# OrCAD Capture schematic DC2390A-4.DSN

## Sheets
1 PAGE1-HSMC: size Custom; title: OVER-SAMPLING ADC MULTI-APPLICATION; rev: 4; note: DEMO CIRCUIT 2390A
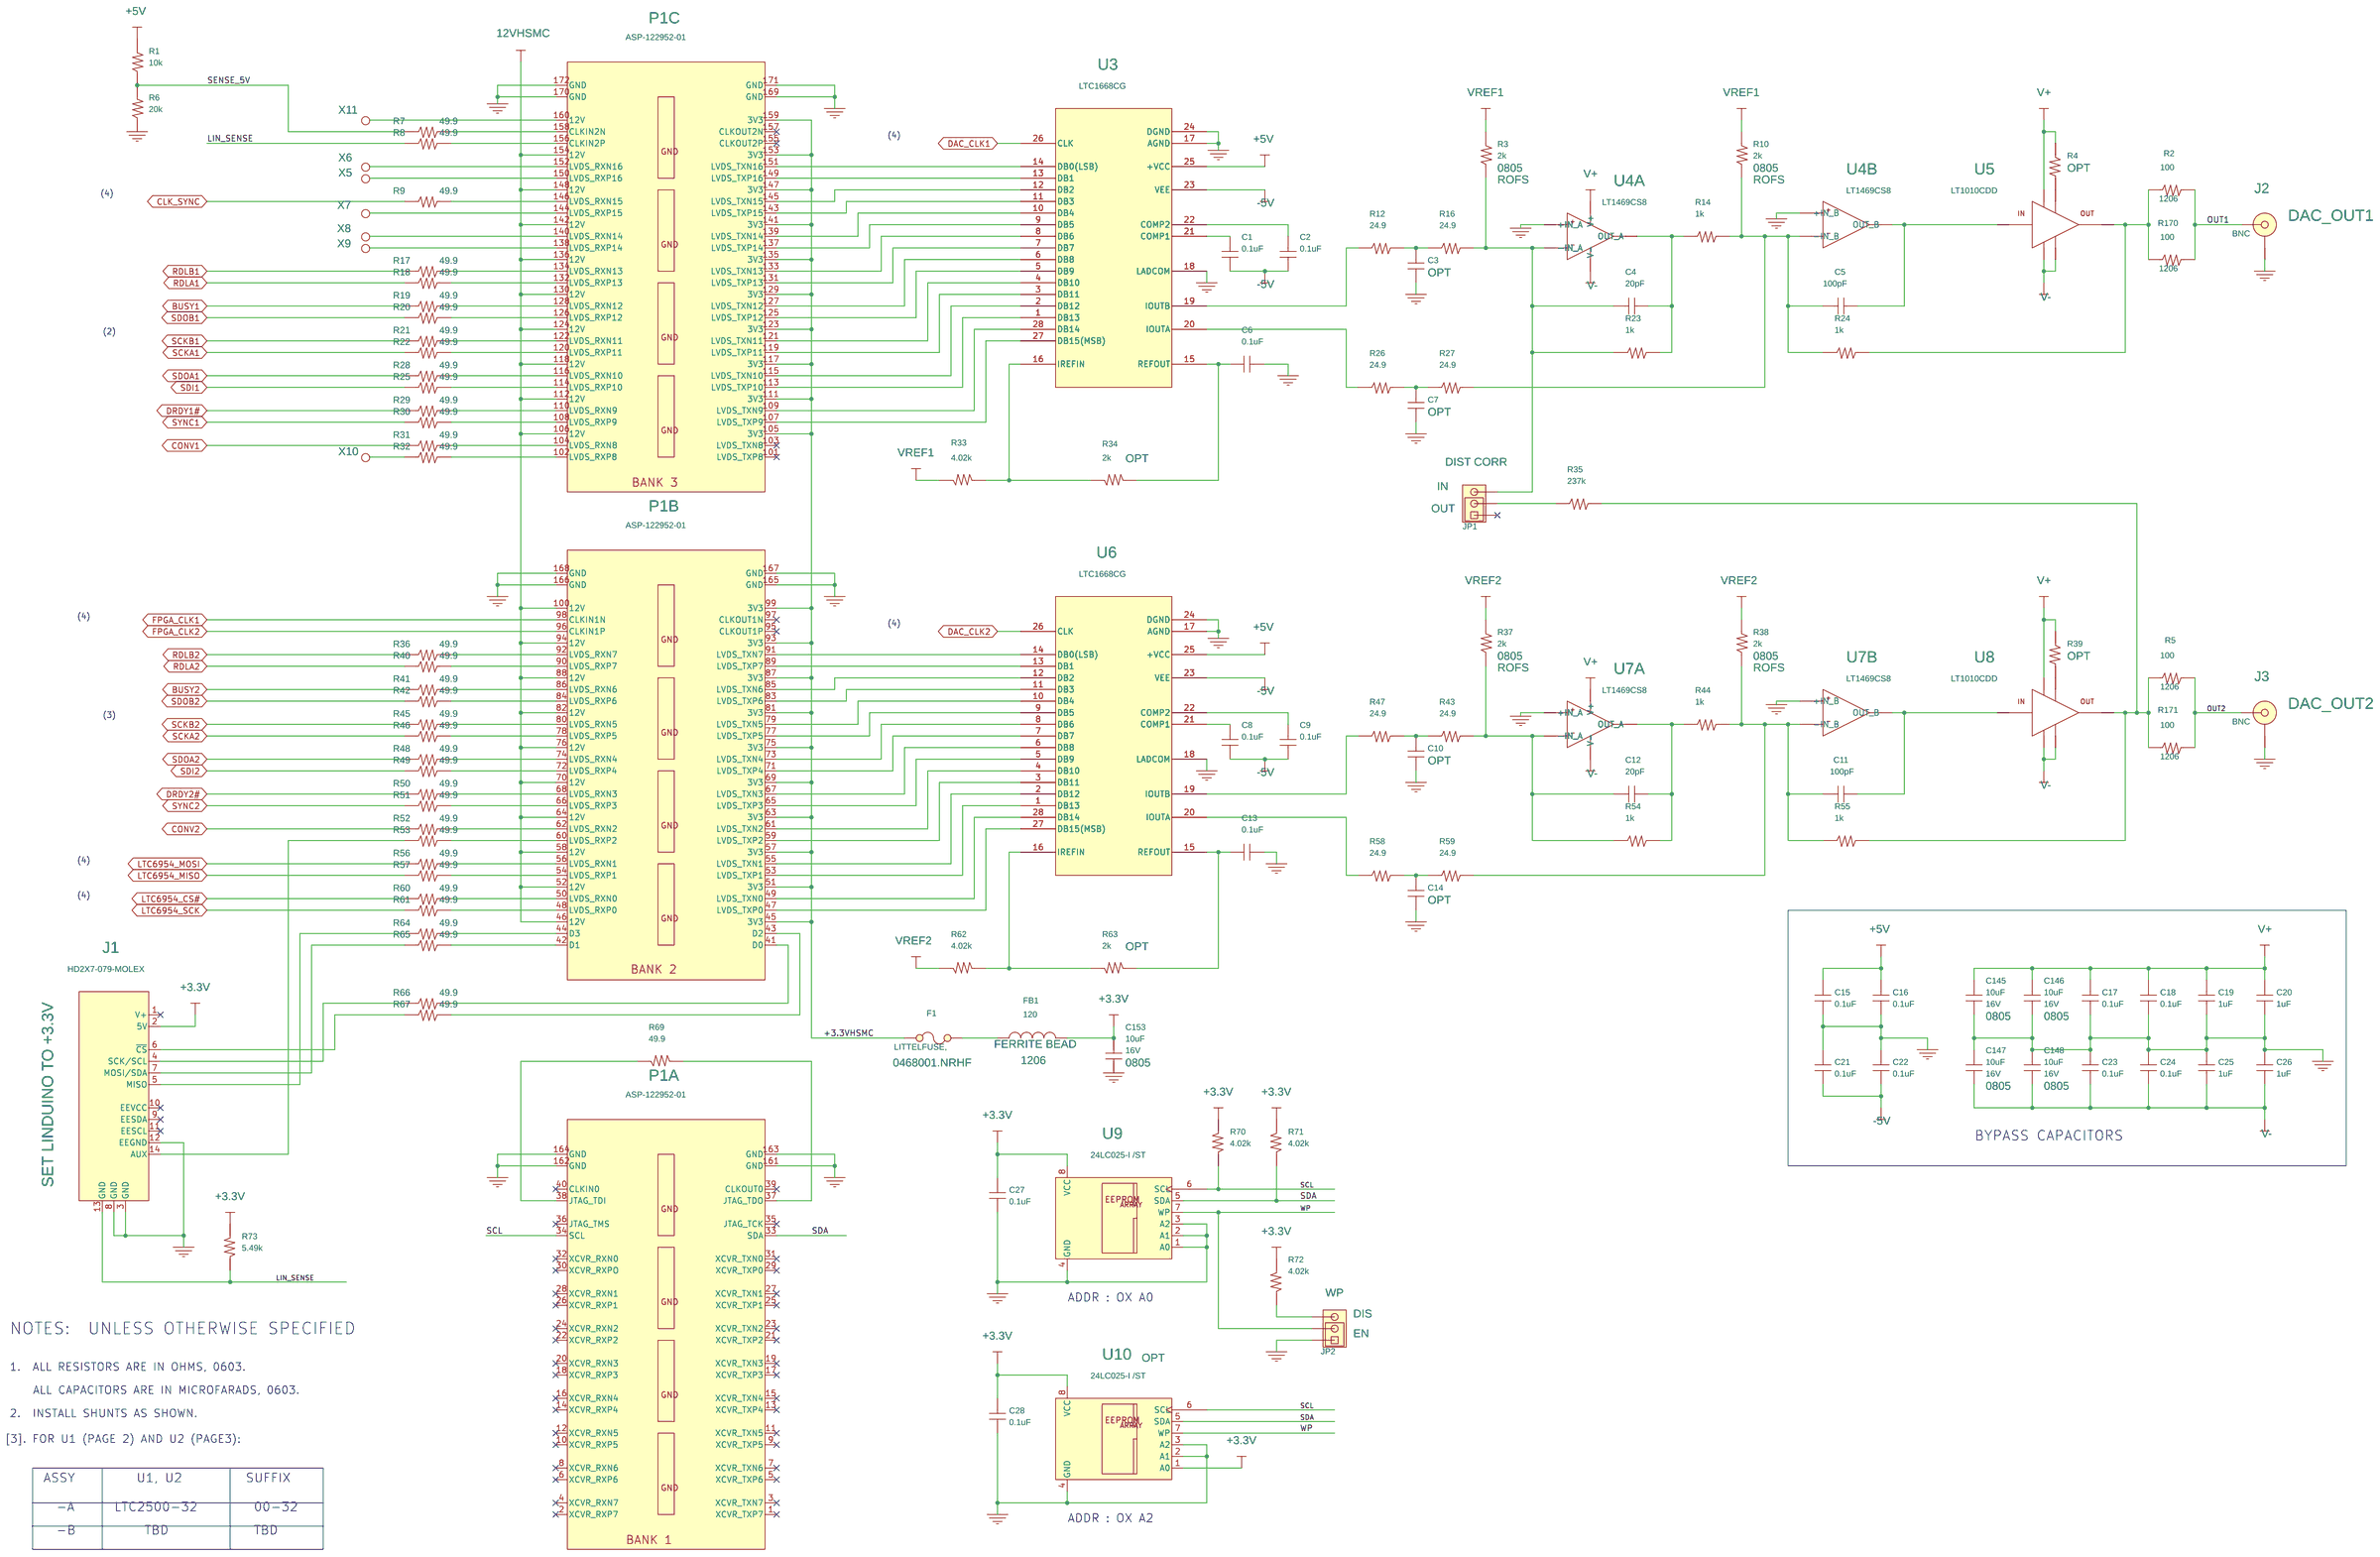
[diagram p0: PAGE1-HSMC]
2 PAGE2-20-BIT SAR ADC 1: size Custom
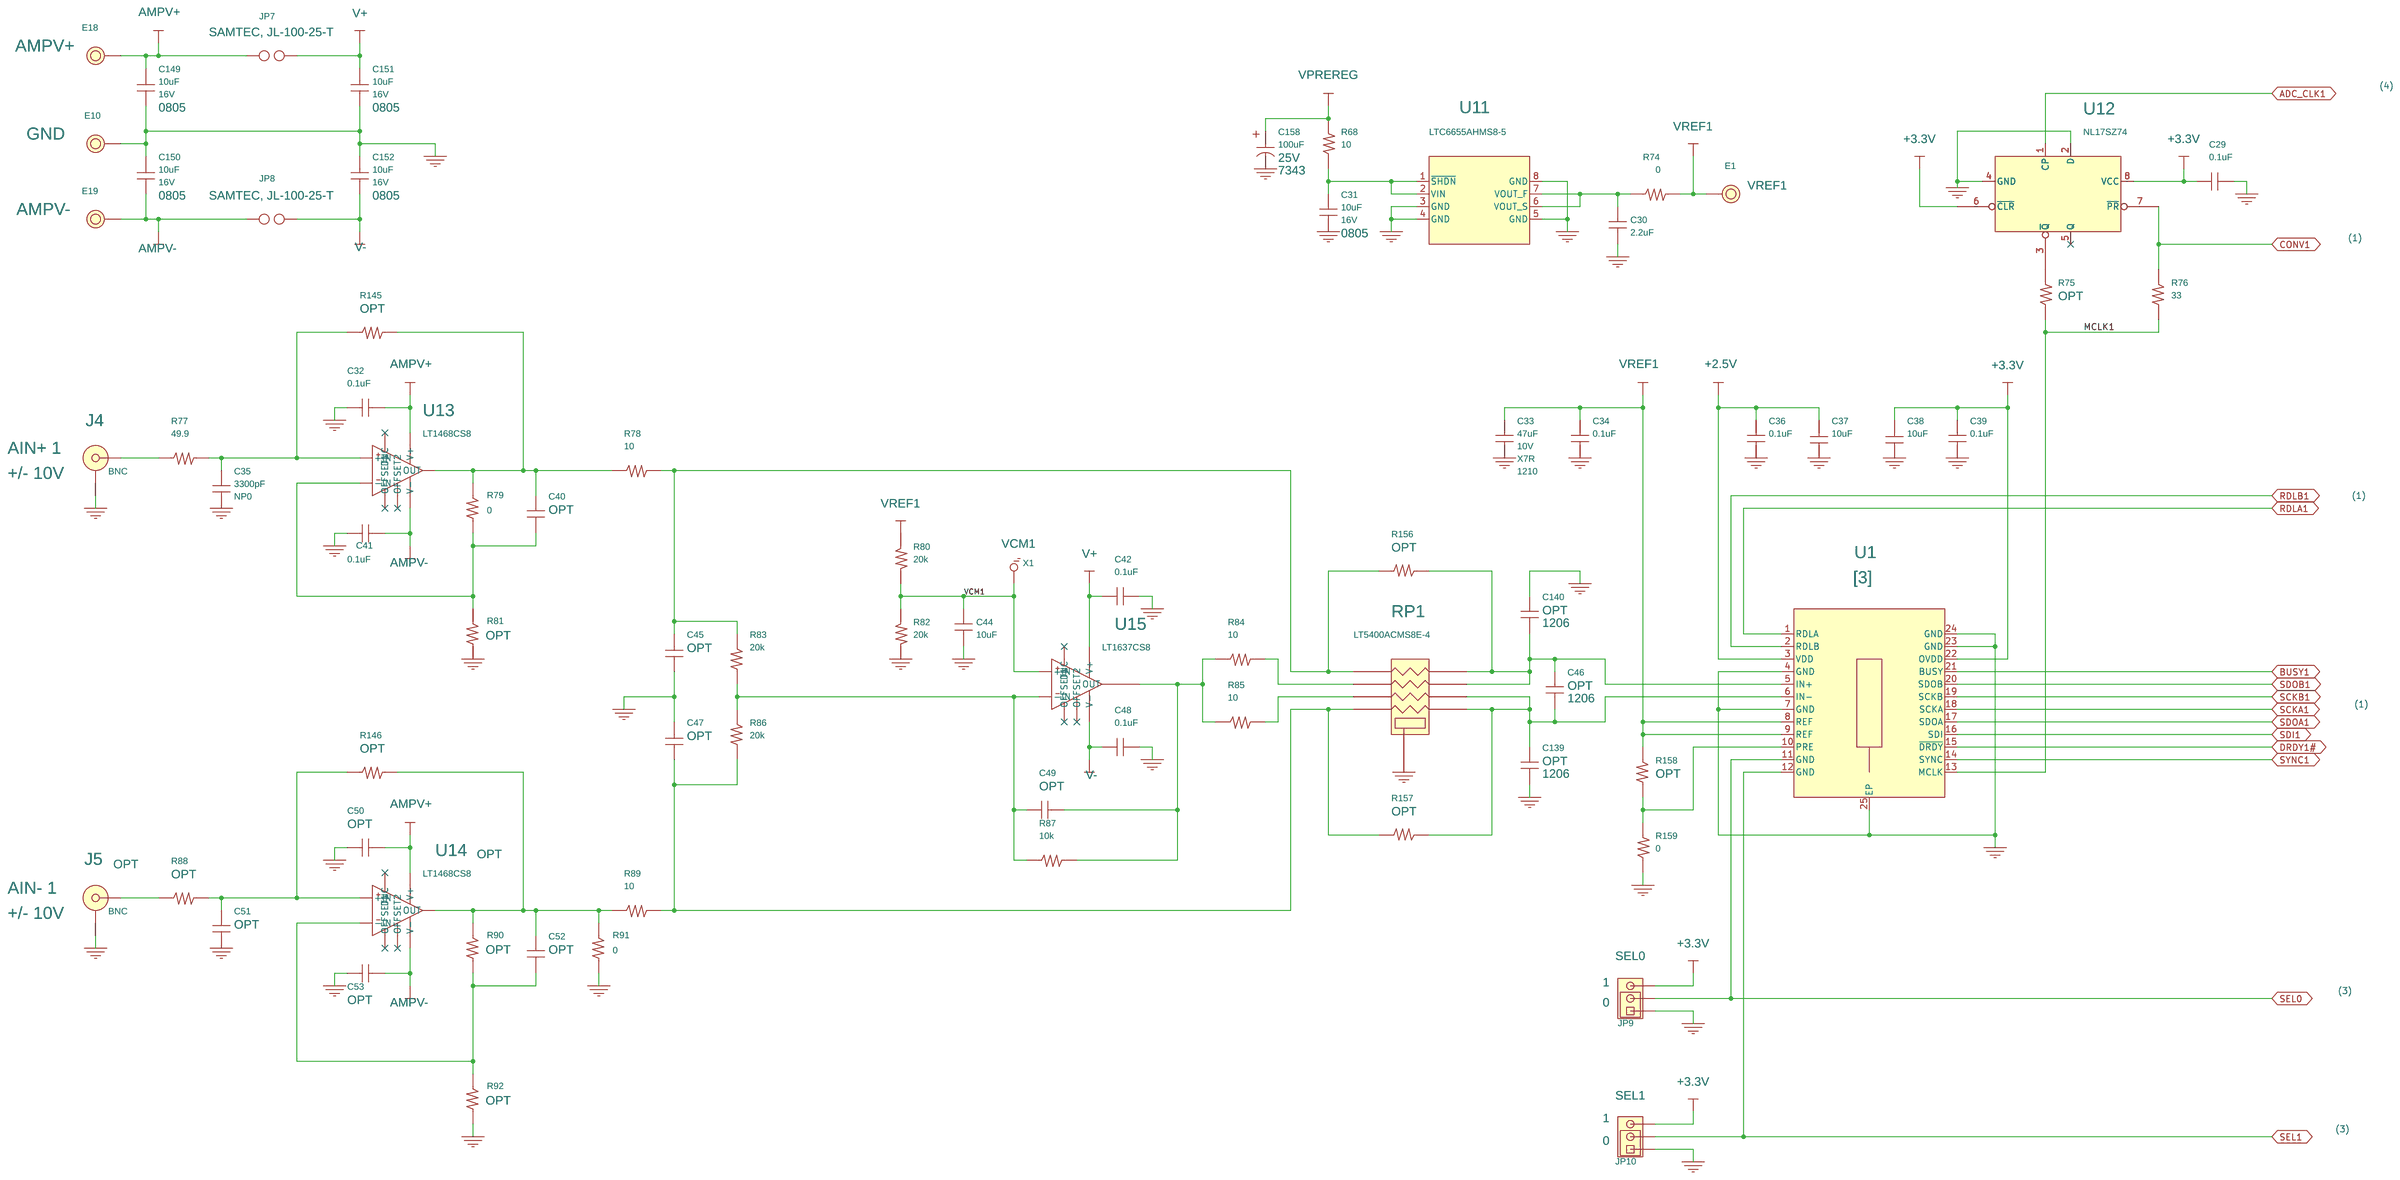
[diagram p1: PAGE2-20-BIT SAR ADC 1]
3 PAGE3-20-BIT SAR ADC 2: size Custom
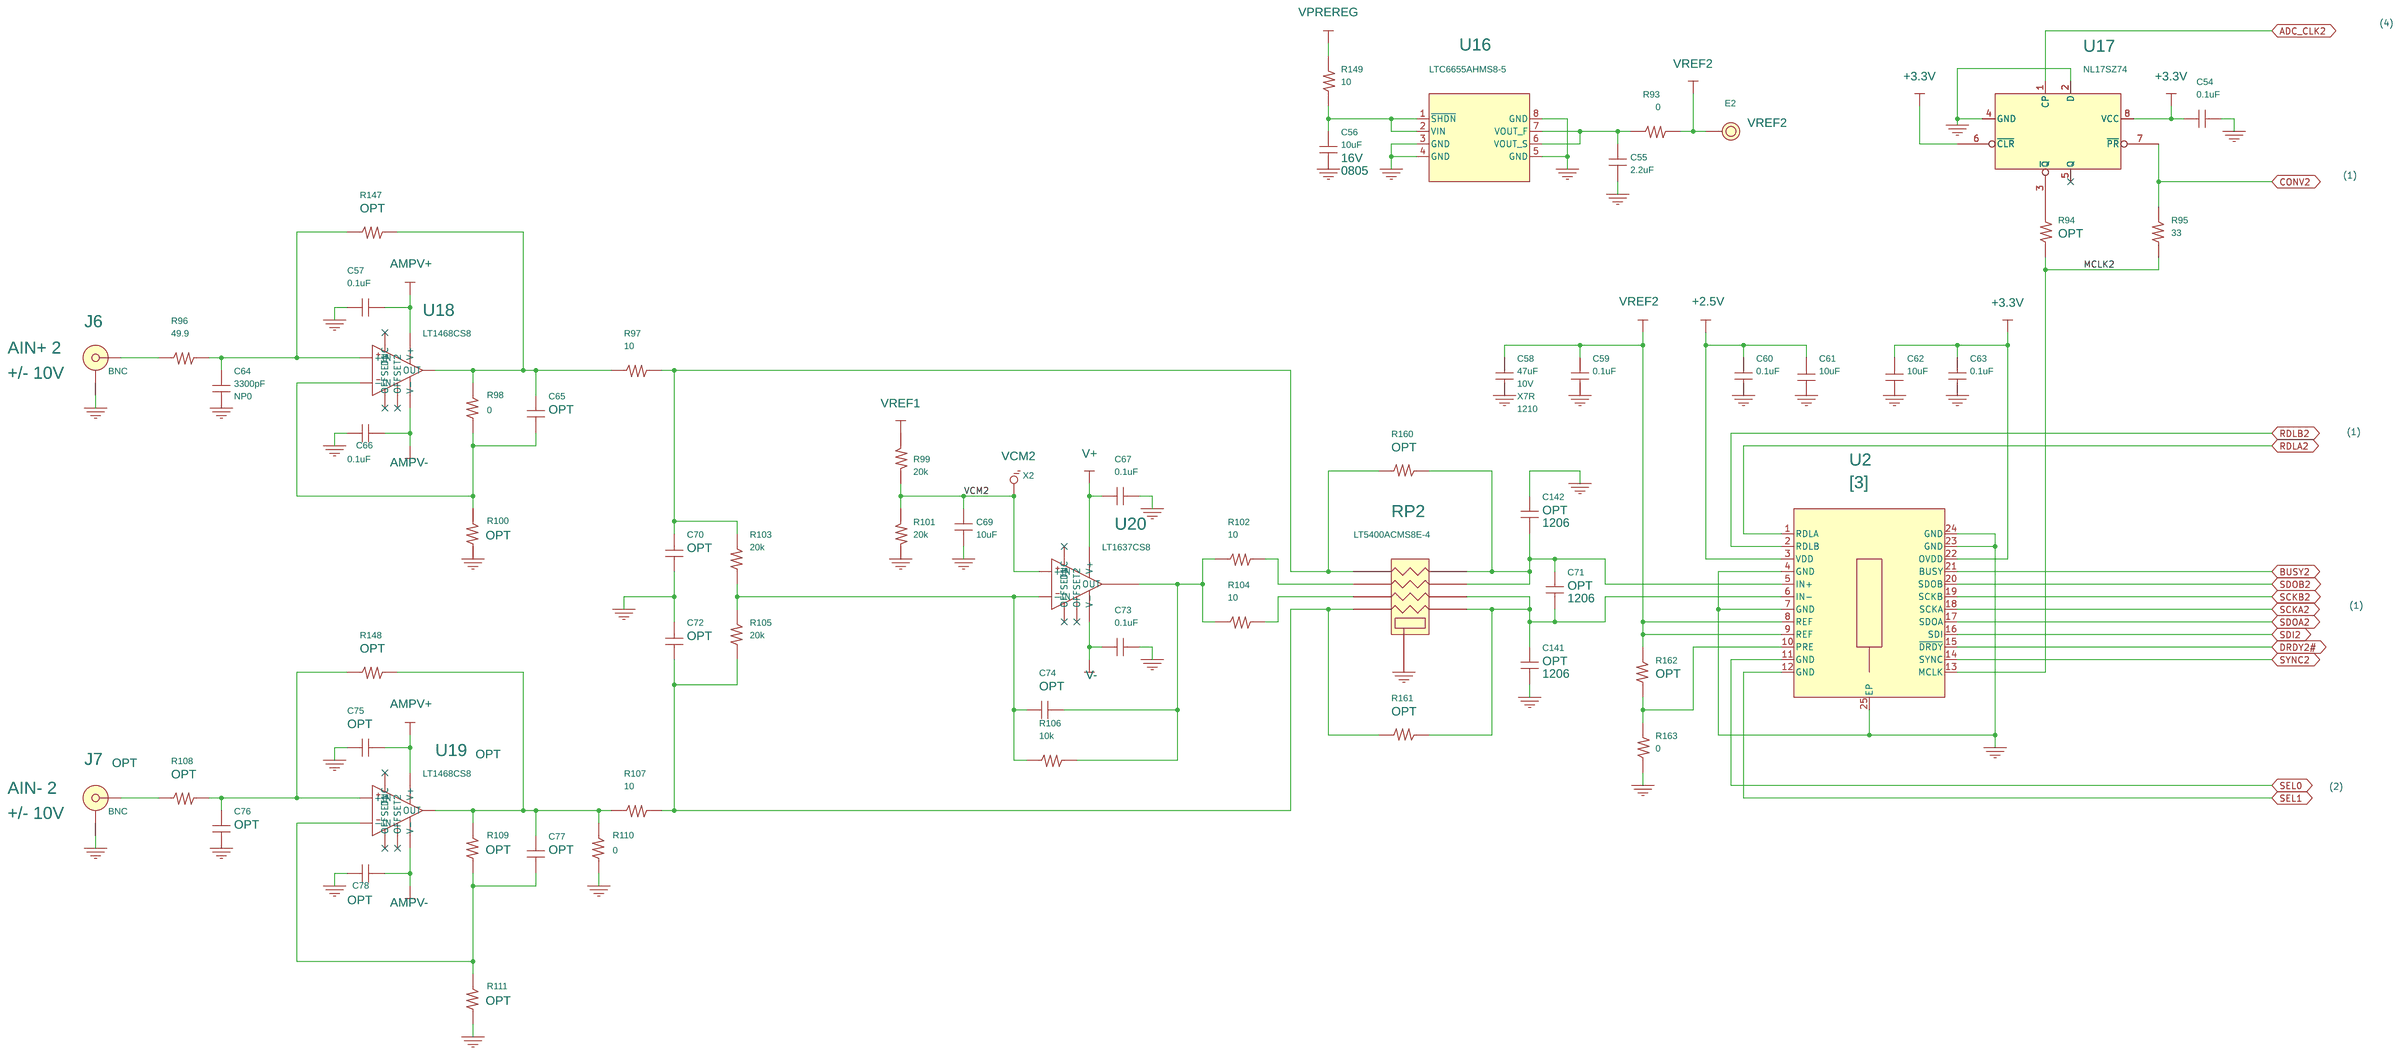
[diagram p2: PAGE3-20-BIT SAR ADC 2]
4 PAGE4-DC1954A: size B
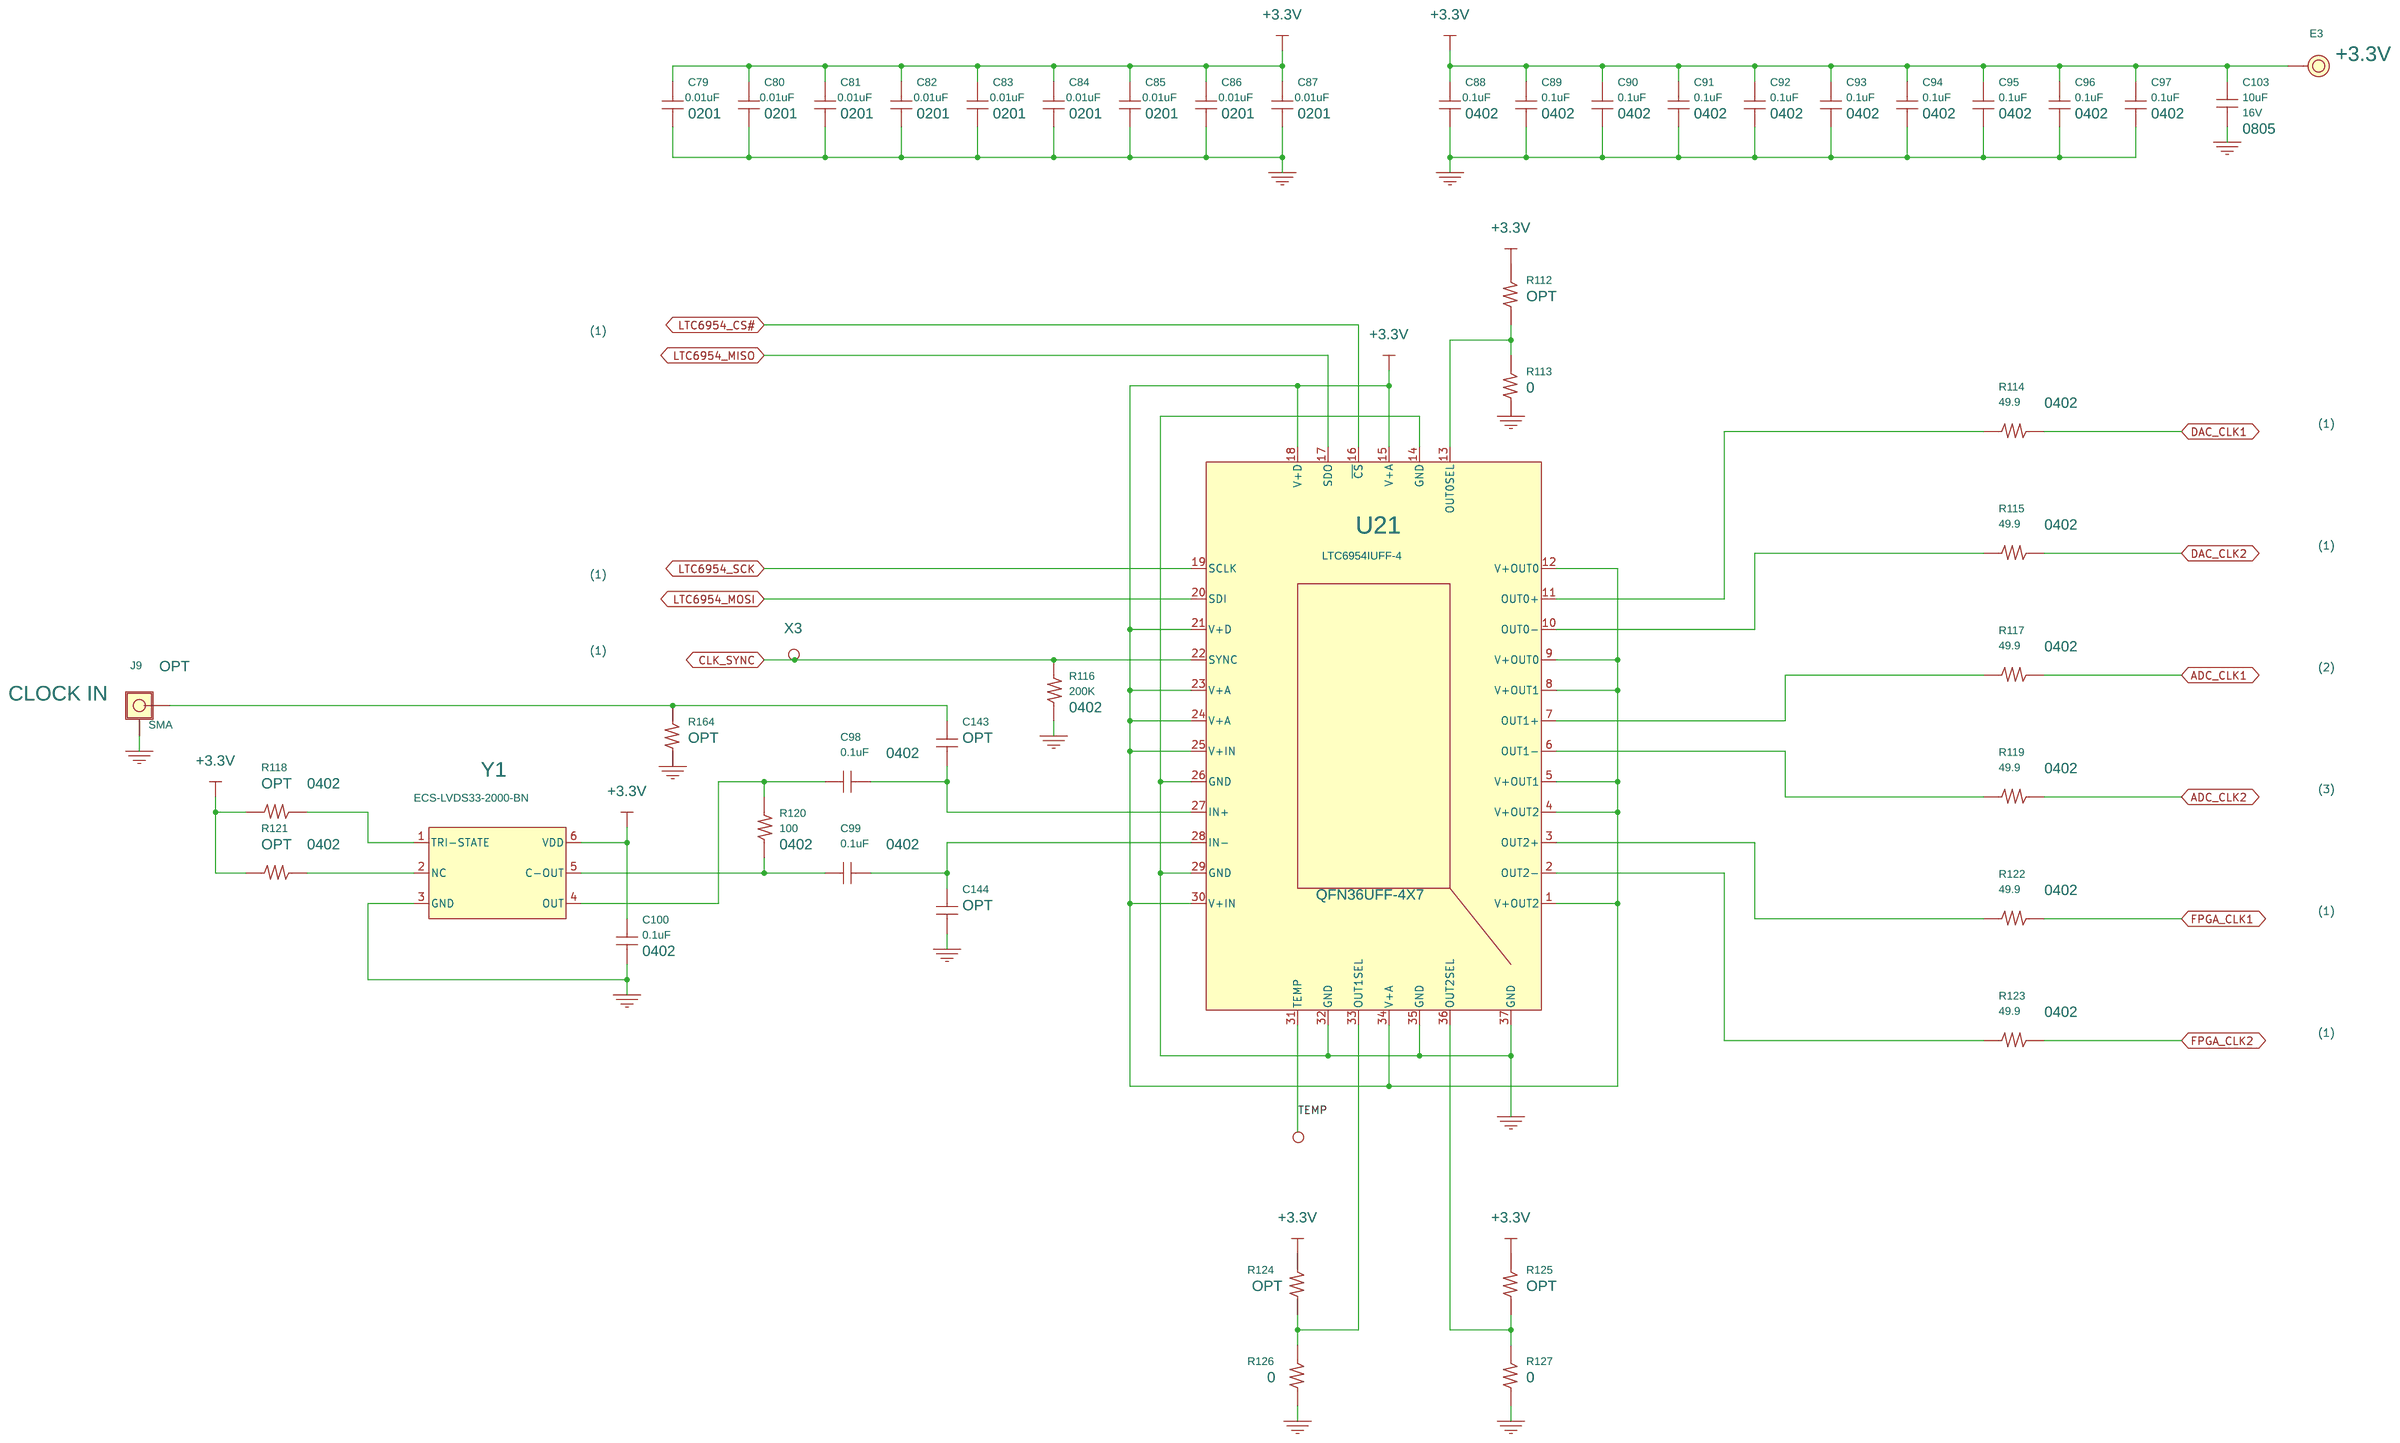
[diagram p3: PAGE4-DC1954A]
5 PAGE5-PWR SUPPLY: size B
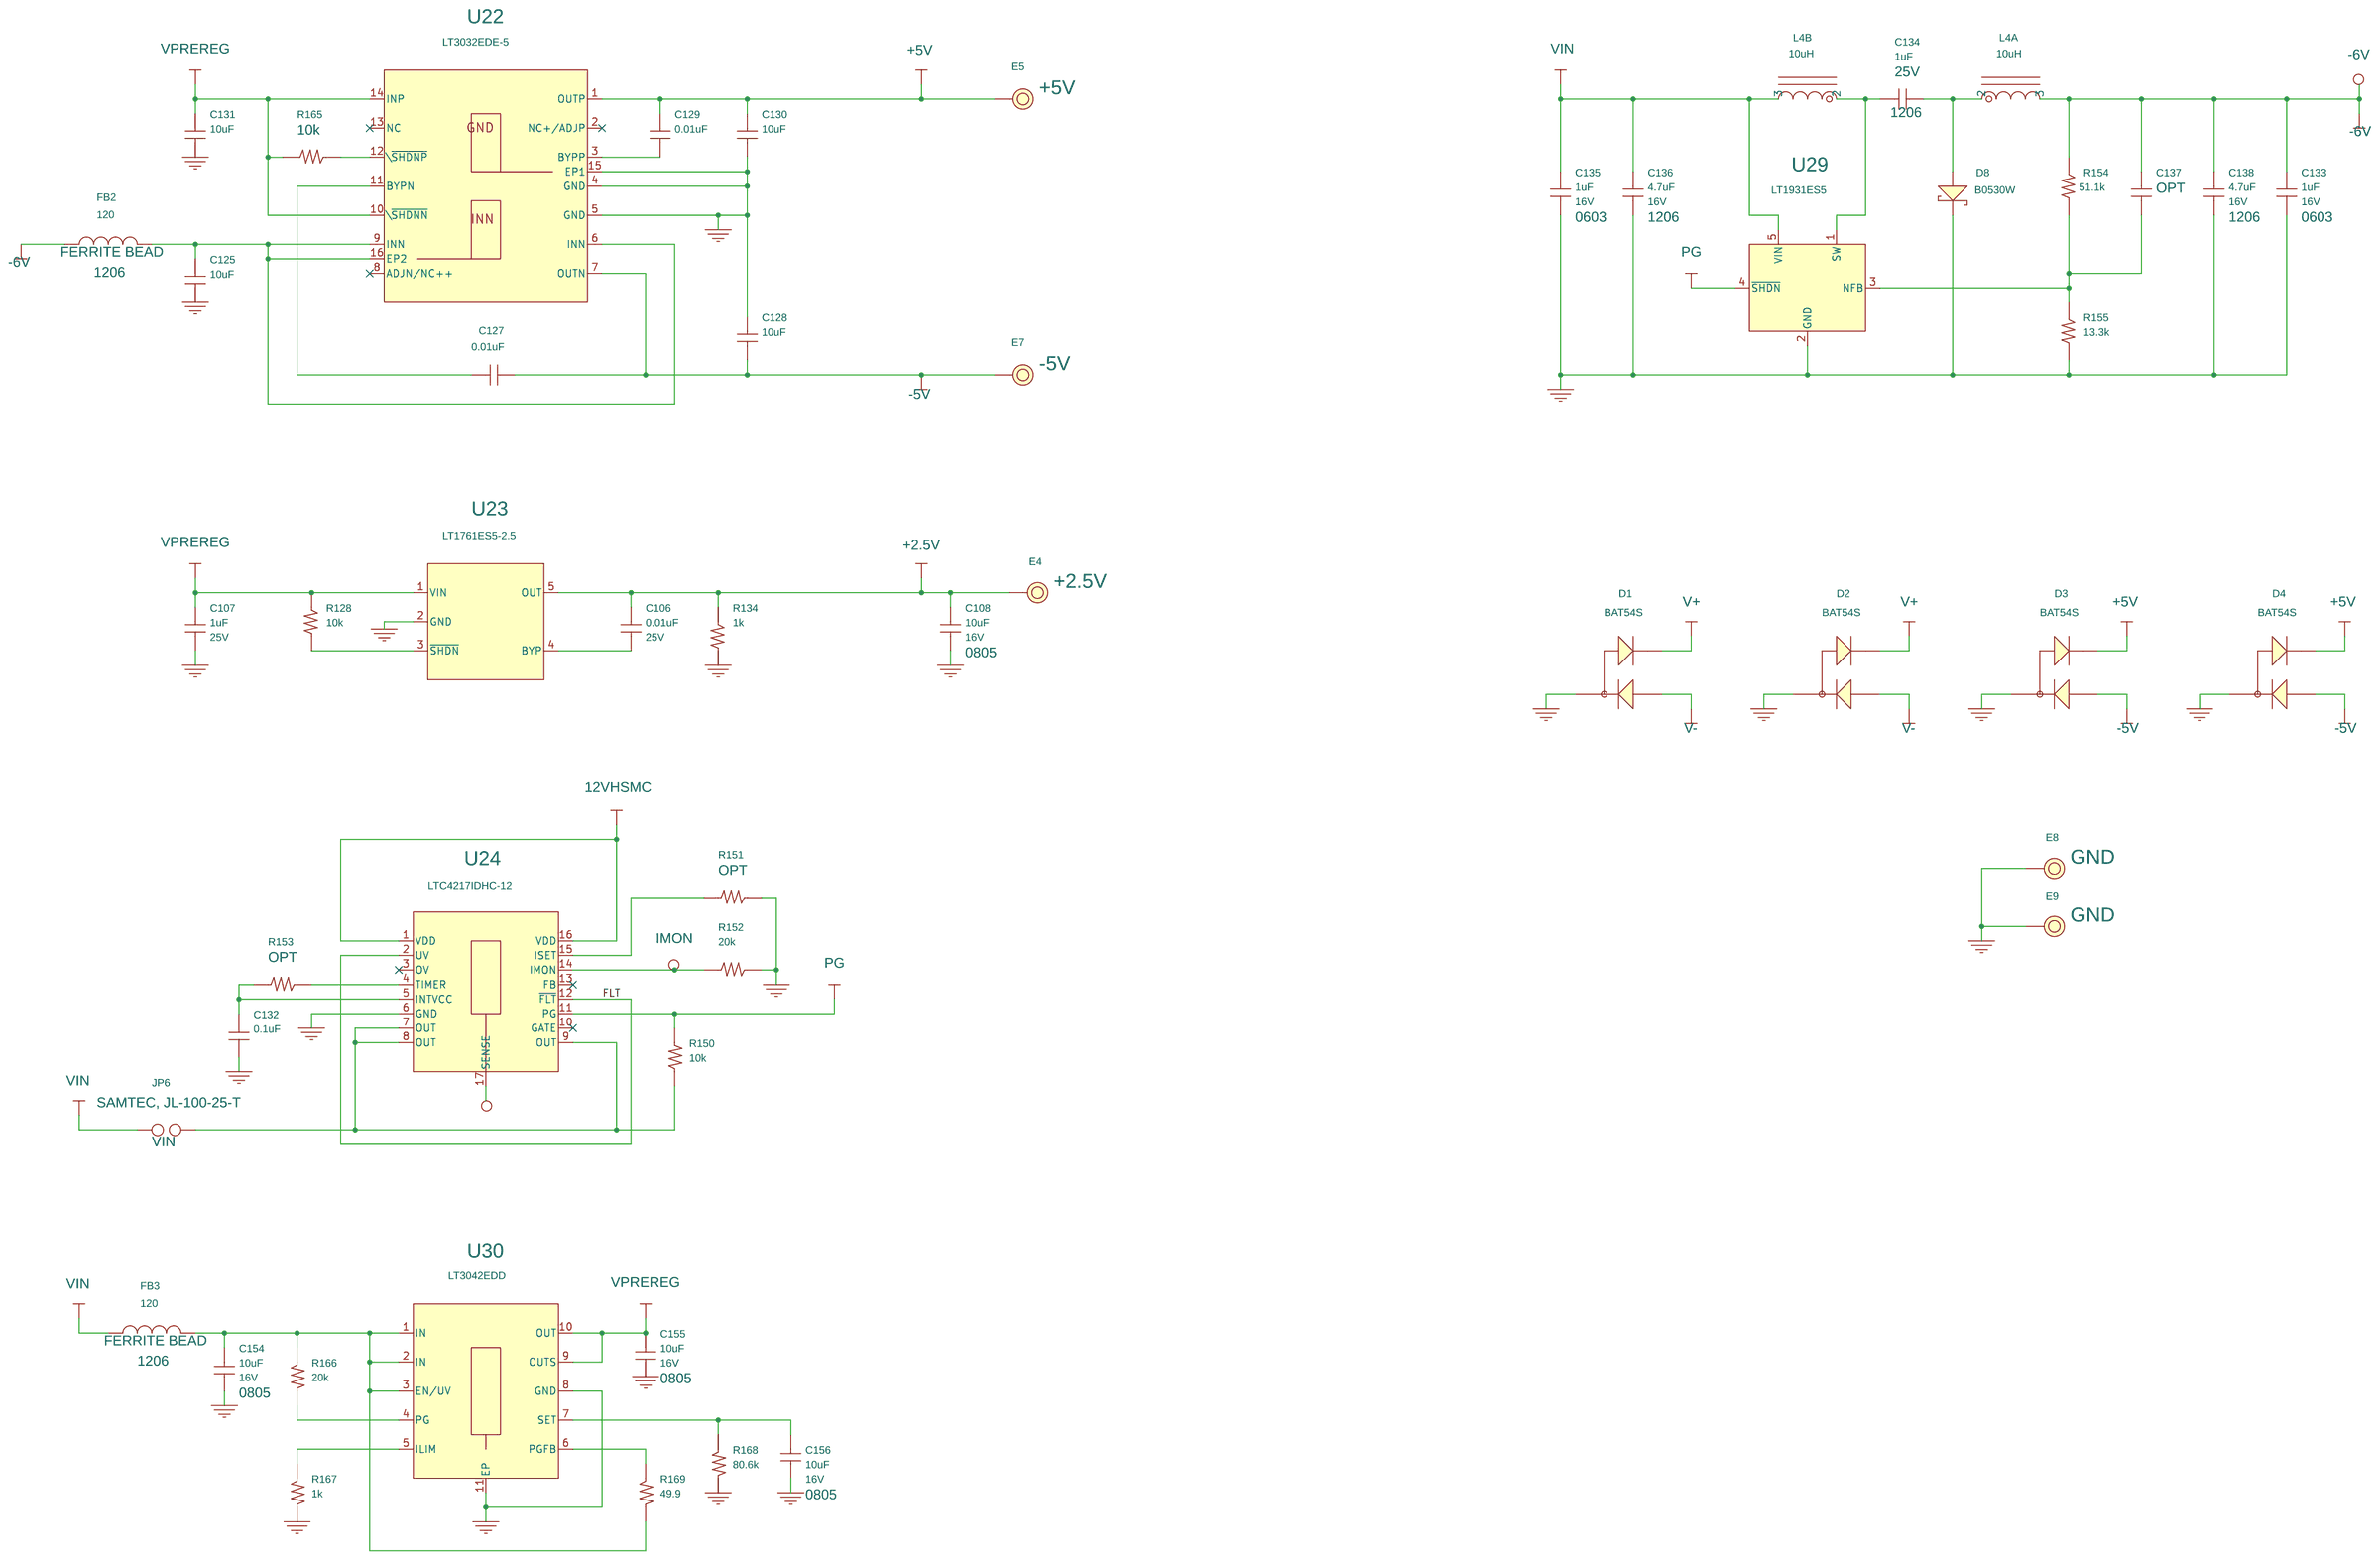
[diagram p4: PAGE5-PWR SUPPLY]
6 PAGE6-DC1280A: size B
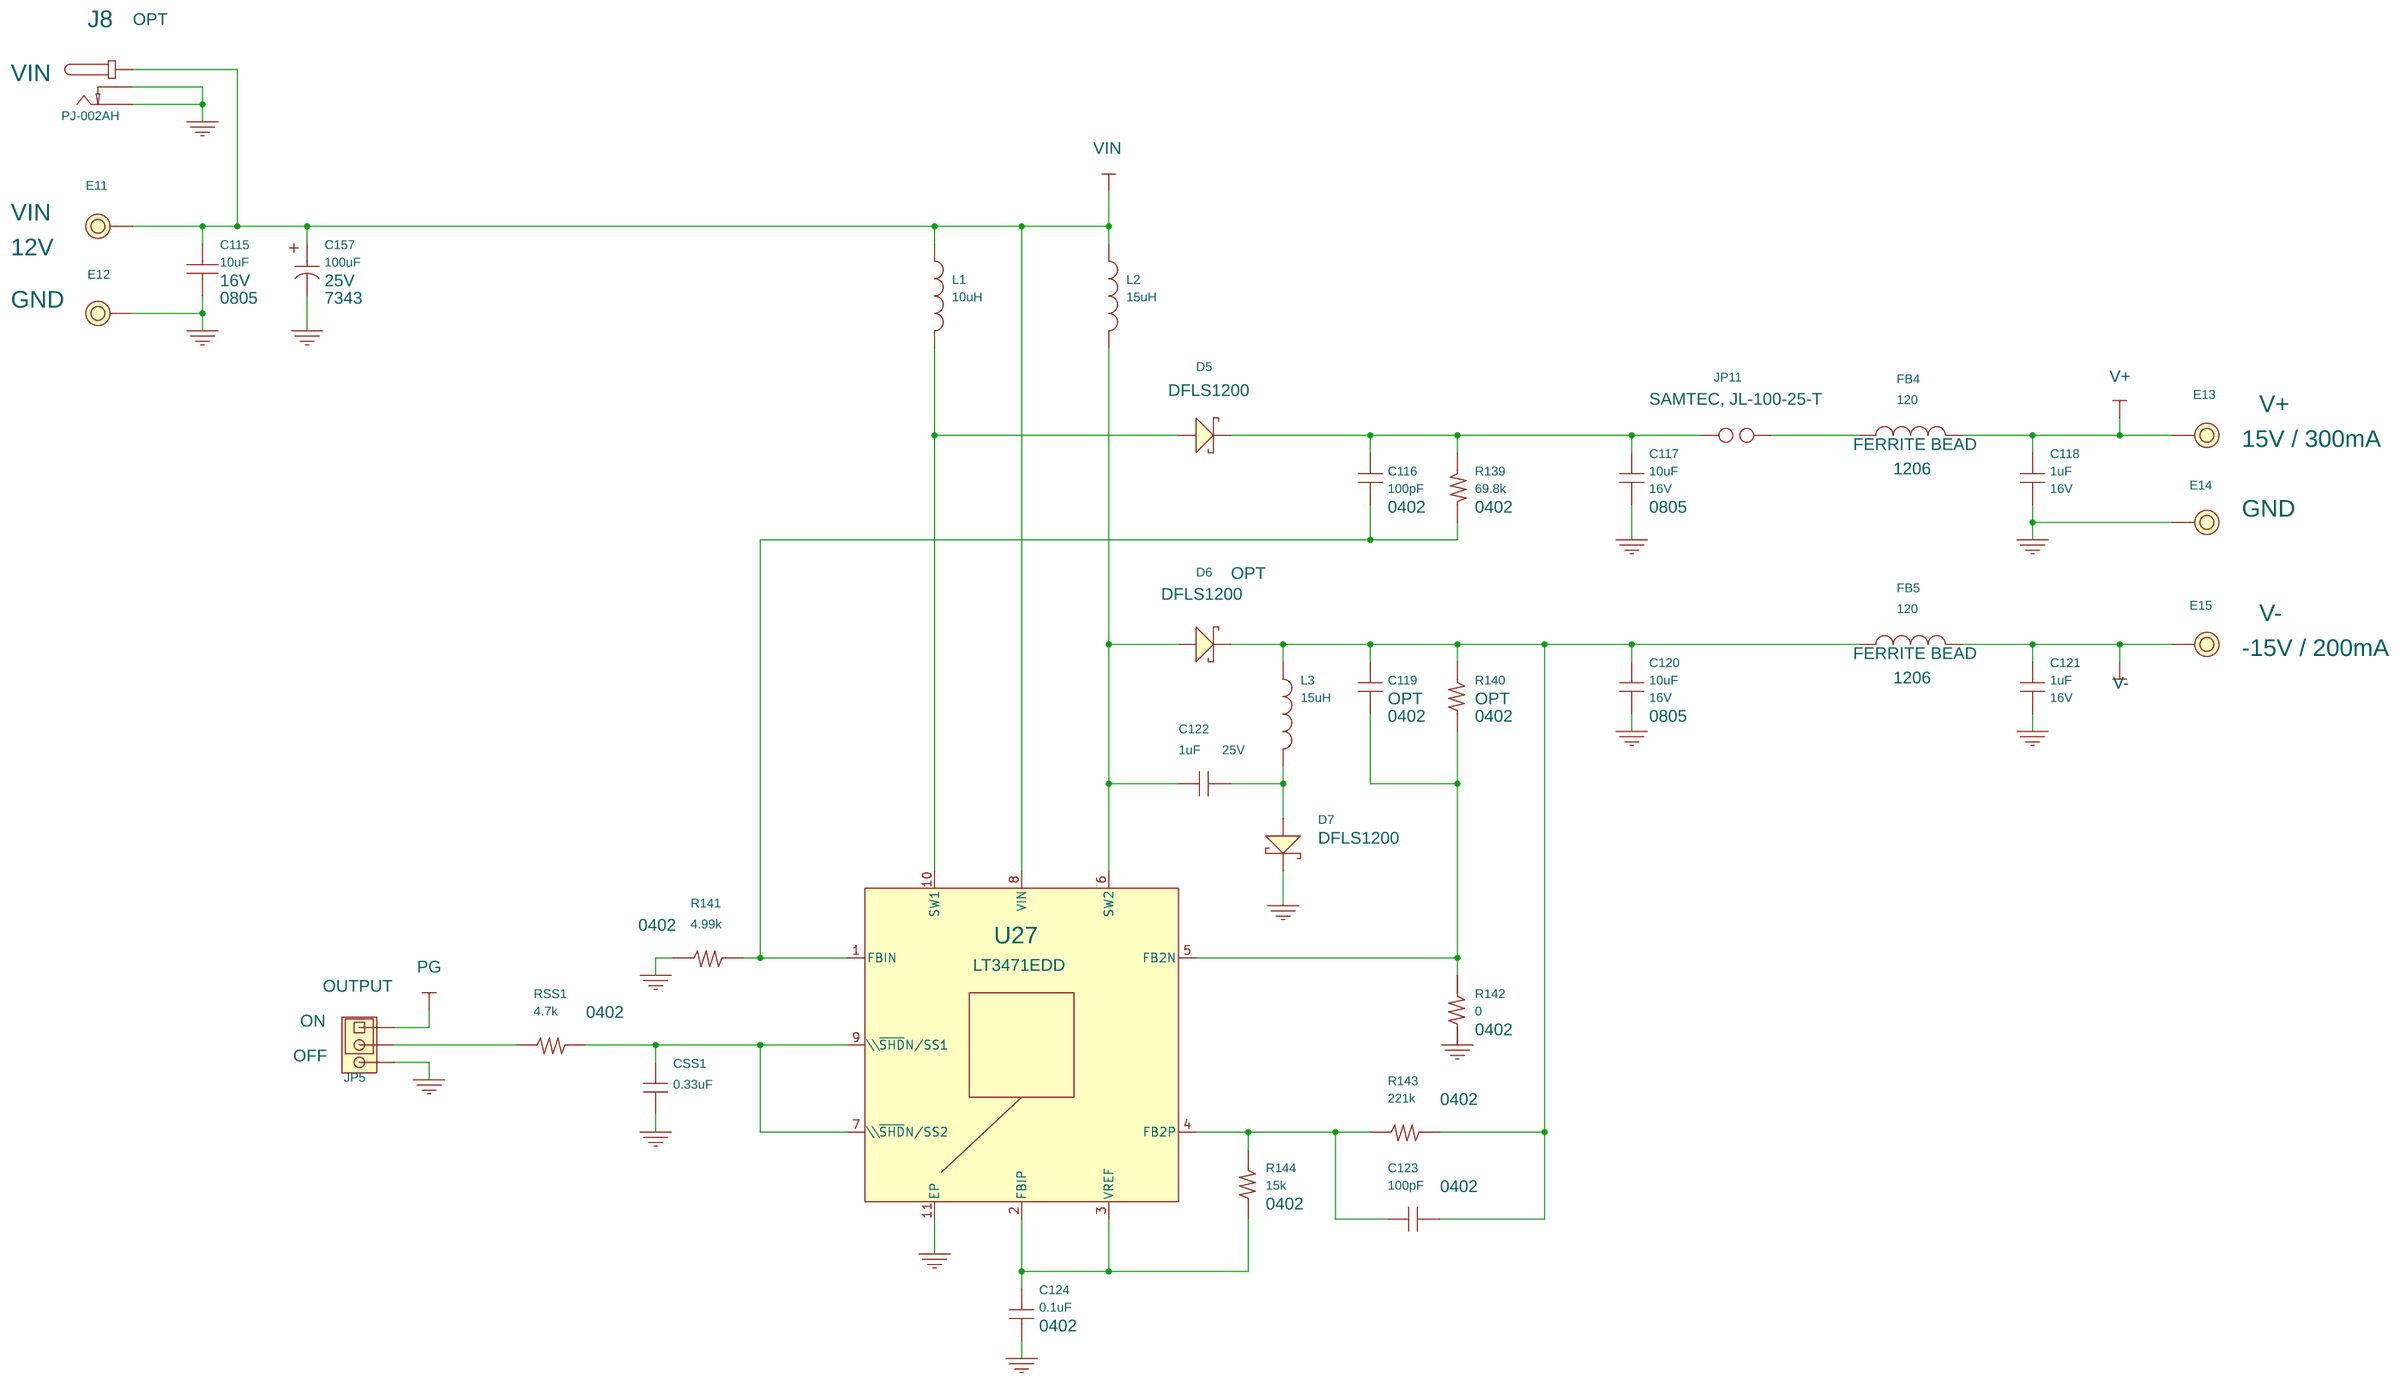
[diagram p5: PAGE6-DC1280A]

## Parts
sheet PAGE1-HSMC
C1  0.1uF  [0603]
C2  0.1uF  [0603]
C3  C-0603  [0603]
C4  20pF  [0603]
C5  100pF  [0603]
C6  0.1uF  [0603]
C7  C-0603  [0603]
C8  0.1uF  [0603]
C9  0.1uF  [0603]
C10  C-0603  [0603]
C11  100pF  [0603]
C12  20pF  [0603]
C13  0.1uF  [0603]
C14  C-0603  [0603]
C15  0.1uF  [0603]
C16  0.1uF  [0603]
C17  0.1uF  [0603]
C18  0.1uF  [0603]
C19  1uF  [0603]
C20  1uF  [0603]
C21  0.1uF  [0603]
C22  0.1uF  [0603]
C23  0.1uF  [0603]
C24  0.1uF  [0603]
C25  1uF  [0603]
C26  1uF  [0603]
C27  0.1uF  [0603]
C28  0.1uF  [0603]
C145  10uF  [0805]
C146  10uF  [0805]
C147  10uF  [0805]
C148  10uF  [0805]
C153  10uF  [0805]
F1  LITTELFUSE,  [FUSE-LITTELFUSE-0468]
FB1  120  [1206]
J1  HD2X7-079-MOLEX  [HD2X7-079-MOLEX]
J2  BNC  [BNC-112404]
J3  BNC  [BNC-112404]
JP1  HD1X3-079  [HD1X3-079]
JP2  HD1X3-079  [HD1X3-079]
P1  ASP-122952-01  [CON-SAMTEC-ASP-122952-01]  (sections A,B,C)
R1  10k  [0603]
R2  100  [1206]
R3  2k  [0805]
R4  R-0603  [0603]
R5  100  [1206]
R6  20k  [0603]
R7  49.9  [0603]
R8  49.9  [0603]
R9  49.9  [0603]
R10  2k  [0805]
R12  24.9  [0603]
R14  1k  [0603]
R16  24.9  [0603]
R17  49.9  [0603]
R18  49.9  [0603]
R19  49.9  [0603]
R20  49.9  [0603]
R21  49.9  [0603]
R22  49.9  [0603]
R23  1k  [0603]
R24  1k  [0603]
R25  49.9  [0603]
R26  24.9  [0603]
R27  24.9  [0603]
R28  49.9  [0603]
R29  49.9  [0603]
R30  49.9  [0603]
R31  49.9  [0603]
R32  49.9  [0603]
R33  4.02k  [0603]
R34  2k  [0603]
R35  237k  [0603]
R36  49.9  [0603]
R37  2k  [0805]
R38  2k  [0805]
R39  R-0603  [0603]
R40  49.9  [0603]
R41  49.9  [0603]
R42  49.9  [0603]
R43  24.9  [0603]
R44  1k  [0603]
R45  49.9  [0603]
R46  49.9  [0603]
R47  24.9  [0603]
R48  49.9  [0603]
R49  49.9  [0603]
R50  49.9  [0603]
R51  49.9  [0603]
R52  49.9  [0603]
R53  49.9  [0603]
R54  1k  [0603]
R55  1k  [0603]
R56  49.9  [0603]
R57  49.9  [0603]
R58  24.9  [0603]
R59  24.9  [0603]
R60  49.9  [0603]
R61  49.9  [0603]
R62  4.02k  [0603]
R63  2k  [0603]
R64  49.9  [0603]
R65  49.9  [0603]
R66  49.9  [0603]
R67  49.9  [0603]
R69  49.9  [0603]
R70  4.02k  [0603]
R71  4.02k  [0603]
R72  4.02k  [0603]
R73  5.49k  [0603]
R170  100  [1206]
R171  100  [1206]
U3  LTC1668CG  [SSOP28]
U4  LT1469CS8  [SO8]  (sections A,B)
U5  LT1010CDD  [DFN8DD-3X3]
U6  LTC1668CG  [SSOP28]
U7  LT1469CS8  [SO8]  (sections A,B)
U8  LT1010CDD  [DFN8DD-3X3]
U9  24LC025-I /ST  [TSSOP8]
U10  24LC025-I /ST  [TSSOP8]
X5  E-SMT-060  [PAD060-SMT-T]
X6  E-SMT-060  [PAD060-SMT-T]
X7  E-SMT-060  [PAD060-SMT-T]
X8  E-SMT-060  [PAD060-SMT-T]
X9  E-SMT-060  [PAD060-SMT-T]
X10  E-SMT-060  [PAD060-SMT-T]
X11  E-SMT-060  [PAD060-SMT-T]
sheet PAGE2-20-BIT SAR ADC 1
C29  0.1uF  [0603]
C30  2.2uF  [0603]
C31  10uF  [0805]
C32  0.1uF  [0603]
C33  47uF  [1210]
C34  0.1uF  [0603]
C35  3300pF  [0603]
C36  0.1uF  [0603]
C37  10uF  [0603]
C38  10uF  [0603]
C39  0.1uF  [0603]
C40  C-0603  [0603]
C41  0.1uF  [0603]
C42  0.1uF  [0603]
C44  10uF  [0603]
C45  C-0603  [0603]
C46  C-1206  [1206]
C47  C-0603  [0603]
C48  0.1uF  [0603]
C49  C-0603  [0603]
C50  C-0603  [0603]
C51  C-0603  [0603]
C52  C-0603  [0603]
C53  C-0603  [0603]
C139  C-1206  [1206]
C140  C-1206  [1206]
C149  10uF  [0805]
C150  10uF  [0805]
C151  10uF  [0805]
C152  10uF  [0805]
C158  100uF  [7343]
E1  MILL-MAX-2308  [MILL-MAX-2308]
E10  MILL-MAX-2308  [MILL-MAX-2308]
E18  MILL-MAX-2308  [MILL-MAX-2308]
E19  MILL-MAX-2308  [MILL-MAX-2308]
J4  BNC  [BNC-112404]
J5  BNC  [BNC-112404]
JP7  SAMTEC, JL-100-25-T  [HD1X2-100]
JP8  SAMTEC, JL-100-25-T  [HD1X2-100]
JP9  HD1X3-079  [HD1X3-079]
JP10  HD1X3-079  [HD1X3-079]
R68  10  [0603]
R74  0  [0603]
R75  R-0603  [0603]
R76  33  [0603]
R77  49.9  [0603]
R78  10  [0603]
R79  0  [0603]
R80  20k  [0603]
R81  R-0603  [0603]
R82  20k  [0603]
R83  20k  [0603]
R84  10  [0603]
R85  10  [0603]
R86  20k  [0603]
R87  10k  [0603]
R88  R-0603  [0603]
R89  10  [0603]
R90  R-0603  [0603]
R91  0  [0603]
R92  R-0603  [0603]
R145  R-0603  [0603]
R146  R-0603  [0603]
R156  R-0603  [0603]
R157  R-0603  [0603]
R158  R-0603  [0603]
R159  0  [0603]
RP1  LT5400ACMS8E-4  [MS8E]
U1  [3]  [DFN24DKD-7X4]
U11  LTC6655AHMS8-5  [MSOP8]
U12  NL17SZ74  [US8]
U13  LT1468CS8  [SO8]
U14  LT1468CS8  [SO8]
U15  LT1637CS8  [SO8]
X1  PAD060-035  [PAD060-035]
sheet PAGE3-20-BIT SAR ADC 2
C54  0.1uF  [0603]
C55  2.2uF  [0603]
C56  10uF  [0805]
C57  0.1uF  [0603]
C58  47uF  [1210]
C59  0.1uF  [0603]
C60  0.1uF  [0603]
C61  10uF  [0603]
C62  10uF  [0603]
C63  0.1uF  [0603]
C64  3300pF  [0603]
C65  C-0603  [0603]
C66  0.1uF  [0603]
C67  0.1uF  [0603]
C69  10uF  [0603]
C70  C-0603  [0603]
C71  C-1206  [1206]
C72  C-0603  [0603]
C73  0.1uF  [0603]
C74  C-0603  [0603]
C75  C-0603  [0603]
C76  C-0603  [0603]
C77  C-0603  [0603]
C78  C-0603  [0603]
C141  C-1206  [1206]
C142  C-1206  [1206]
E2  MILL-MAX-2308  [MILL-MAX-2308]
J6  BNC  [BNC-112404]
J7  BNC  [BNC-112404]
R93  0  [0603]
R94  R-0603  [0603]
R95  33  [0603]
R96  49.9  [0603]
R97  10  [0603]
R98  0  [0603]
R99  20k  [0603]
R100  R-0603  [0603]
R101  20k  [0603]
R102  10  [0603]
R103  20k  [0603]
R104  10  [0603]
R105  20k  [0603]
R106  10k  [0603]
R107  10  [0603]
R108  R-0603  [0603]
R109  R-0603  [0603]
R110  0  [0603]
R111  R-0603  [0603]
R147  R-0603  [0603]
R148  R-0603  [0603]
R149  10  [0603]
R160  R-0603  [0603]
R161  R-0603  [0603]
R162  R-0603  [0603]
R163  0  [0603]
RP2  LT5400ACMS8E-4  [MS8E]
U2  [3]  [DFN24DKD-7X4]
U16  LTC6655AHMS8-5  [MSOP8]
U17  NL17SZ74  [US8]
U18  LT1468CS8  [SO8]
U19  LT1468CS8  [SO8]
U20  LT1637CS8  [SO8]
X2  PAD060-035  [PAD060-035]
sheet PAGE4-DC1954A
C79  0.01uF  [0201]
C80  0.01uF  [0201]
C81  0.01uF  [0201]
C82  0.01uF  [0201]
C83  0.01uF  [0201]
C84  0.01uF  [0201]
C85  0.01uF  [0201]
C86  0.01uF  [0201]
C87  0.01uF  [0201]
C88  0.1uF  [0402]
C89  0.1uF  [0402]
C90  0.1uF  [0402]
C91  0.1uF  [0402]
C92  0.1uF  [0402]
C93  0.1uF  [0402]
C94  0.1uF  [0402]
C95  0.1uF  [0402]
C96  0.1uF  [0402]
C97  0.1uF  [0402]
C98  0.1uF  [0402]
C99  0.1uF  [0402]
C100  0.1uF  [0402]
C103  10uF  [0805]
C143  C-0603  [0603]
C144  C-0603  [0603]
E3  MILL-MAX-2308  [MILL-MAX-2308]
J9  SMA  [CON-SMA-SMT-JOHNSON-142-0711]
R112  R-0603  [0603]
R113  0  [0603]
R114  49.9  [0402]
R115  49.9  [0402]
R116  200K  [0402]
R117  49.9  [0402]
R118  R-0402  [0402]
R119  49.9  [0402]
R120  100  [0402]
R121  R-0402  [0402]
R122  49.9  [0402]
R123  49.9  [0402]
R124  R-0603  [0603]
R125  R-0603  [0603]
R126  0  [0603]
R127  0  [0603]
R164  R-0603  [0603]
U21  LTC6954IUFF-4  [QFN36UFF-4X7]
X3  E-SMT-060  [PAD060-SMT-T]
X4  E-SMT-060  [PAD060-SMT-T]
Y1  ECS-LVDS33-2000-BN  [Y-ECS-LVDS33-2000-BN]
sheet PAGE5-PWR SUPPLY
-6V  E-SMT-060  [PAD060-SMT-T]
C106  0.01uF  [0603]
C107  1uF  [0603]
C108  10uF  [0805]
C125  10uF  [0603]
C127  0.01uF  [0603]
C128  10uF  [0603]
C129  0.01uF  [0603]
C130  10uF  [0603]
C131  10uF  [0603]
C132  0.1uF  [0603]
C133  1uF  [0603]
C134  1uF  [1206]
C135  1uF  [0603]
C136  4.7uF  [1206]
C137  C-0603  [0603]
C138  4.7uF  [1206]
C154  10uF  [0805]
C155  10uF  [0805]
C156  10uF  [0805]
D1  BAT54S  [SOT23]
D2  BAT54S  [SOT23]
D3  BAT54S  [SOT23]
D4  BAT54S  [SOT23]
D8  B0530W  [SOD123]
E4  MILL-MAX-2308  [MILL-MAX-2308]
E5  MILL-MAX-2308  [MILL-MAX-2308]
E7  MILL-MAX-2308  [MILL-MAX-2308]
E8  MILL-MAX-2308  [MILL-MAX-2308]
E9  MILL-MAX-2308  [MILL-MAX-2308]
FB2  120  [1206]
FB3  120  [1206]
IMON  E-SMT-060  [PAD060-SMT-T]
JP6  SAMTEC, JL-100-25-T  [HD1X2-100]
L4  10uH  [L-CLS62]  (sections A,B)
R128  10k  [0603]
R134  1k  [0603]
R150  10k  [0603]
R151  R-0603  [0603]
R152  20k  [0603]
R153  R-0603  [0603]
R154  51.1k  [0603]
R155  13.3k  [0603]
R165  10k  [0603]
R166  20k  [0603]
R167  1k  [0603]
R168  80.6k  [0603]
R169  49.9  [0603]
TP1  E-SMT-060  [PAD060-SMT-T]
U22  LT3032EDE-5  [DFN14DEMA-4X3]
U23  LT1761ES5-2.5  [SOT23-5]
U24  LTC4217IDHC-12  [DFN16DHC-5X3]
U29  LT1931ES5  [SOT23-5]
U30  LT3042EDD  [DFN10DD-3X3]
sheet PAGE6-DC1280A
C115  10uF  [0805]
C116  100pF  [0402]
C117  10uF  [0805]
C118  1uF  [0603]
C119  C-0402  [0402]
C120  10uF  [0805]
C121  1uF  [0603]
C122  1uF  [0603]
C123  100pF  [0402]
C124  0.1uF  [0402]
C157  100uF  [7343]
CSS1  0.33uF  [0603]
D5  DFLS1200  [POWERDI123]
D6  DFLS1200  [POWERDI123]
D7  DFLS1200  [POWERDI123]
E11  MILL-MAX-2308  [MILL-MAX-2308]
E12  MILL-MAX-2308  [MILL-MAX-2308]
E13  MILL-MAX-2308  [MILL-MAX-2308]
E14  MILL-MAX-2308  [MILL-MAX-2308]
E15  MILL-MAX-2308  [MILL-MAX-2308]
FB4  120  [1206]
FB5  120  [1206]
J8  PJ-002AH  [CON-CUI-PJ002AH]
JP5  HD1X3-079  [HD1X3-079]
JP11  SAMTEC, JL-100-25-T  [HD1X2-100]
L1  10uH  [L-NR4018]
L2  15uH  [L-NR4018]
L3  15uH  [L-NR4018]
R139  69.8k  [0402]
R140  R-0402  [0402]
R141  4.99k  [0402]
R142  0  [0402]
R143  221k  [0402]
R144  15k  [0402]
RSS1  4.7k  [0402]
U27  LT3471EDD  [DFN10DD-3X3]

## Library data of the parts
C1 C2 C4-C6 C8 C9 C11-C13 C15-C28 C106 C107 C127 C129 C132 = CAP-NP: Voltage: 25V
C3 C7 C10 C14 = CAP-NP: OPT: OPT; Voltage: 25V
C31 C103 C108 C117 C120 C145-C156 = CAP-NP: Voltage: 16V
F1 = FUSE: 1ST PART FIELD: 0468001.NRHF
FB1-FB5 = IND: 1ST PART FIELD: BLM31PG121SN1; 2ND PART FIELD: FERRITE BEAD
J1 = HD2X7-079-MOLEX: PART FIELD 1: SET LINDUINO TO +3.3V
J2 = BNC_1: CONNECTOR, BNC; PART FIELD 1: DAC_OUT1; Part Number: CONNEX, 112404
J3 = BNC_1: CONNECTOR, BNC; PART FIELD 1: DAC_OUT2; Part Number: CONNEX, 112404
JP1 = HD1X3: PART FIELD 1: DIST CORR; PART FIELD 2: OUT; PART FIELD 3: IN
JP2 = HD1X3: PART FIELD 1: WP; PART FIELD 2: EN; PART FIELD 3: DIS
P1 = CON-HSMC-ASP-122952-01
R1 R2 R5-R9 R12 R14 R16-R33 R35 R36 R40-R62 R64-R74 R76-R80 R82-R87 R89 R91 R93 R95-R99 R101-R107 R110 R113-R117 R119 R120 R122 R123 R126-R128 R134 R142 R144 R149 R150 R152 R154 R155 R159 R163 R165-R171 RSS1 = R
R3 R10 R37 R38 = R: 1ST PART FIELD: ROFS
R4 R34 R39 R63 R75 R81 R88 R90 R92 R94 R100 R108 R109 R111 R112 R118 R121 R124 R125 R140 R145-R148 R151 R153 R156-R158 R160-R162 R164 = R: OPT: OPT
U3 U6 = LTC1668CG-SSOP28-VEE
U4 U7 = LT1469CS8
U5 U8 = LT1010CDD-DFN8DD-3X3
U9 = 24LC025-I_ST
U10 = 24LC025-I_ST: OPT: OPT
-6V IMON TP1 X3-X11 = E-SMT-060
C29 C30 C32 C34 C36 C39 C41 C42 C48 C54 C55 C57 C59 C60 C63 C66 C67 C73 C79-C100 C116 C123 C124 CSS1 = CAP-NP
C33 C58 = CAP-NP: DIELECTRIC: X7R; Voltage: 10V
C35 C64 = CAP-NP: DIELECTRIC: NP0
C37 C38 C61 C62 C125 C128 C130 C131 = CAP-NP: Voltage: 6.3V
C40 C46 C49-C53 C65 C71 C74-C78 C119 C139-C144 = CAP-NP: OPT: OPT
C44 = CAP-NP: PART FIELD 1: 6.3V; VOLTAGE: 6.3V
C45 C47 C70 C72 = CAP-NP: DIELECTRIC: NP0; OPT: OPT
C157 C158 = CAP: VOLTAGE: 25V
E1 = E-064: PART FIELD 1: VREF1
E8-E10 = E-064: PART FIELD 1: GND
E18 = E-064: PART FIELD 1: AMPV+
E19 = E-064: PART FIELD 1: AMPV-
J4 = BNC_1: CONNECTOR, BNC; PART FIELD 1: AIN+ 1; PART FIELD 2: +/- 10V; Part Number: CONNEX, 112404
J5 = BNC_1: CONNECTOR, BNC; OPT: OPT; PART FIELD 1: AIN- 1; PART FIELD 2: +/- 10V; Part Number: CONNEX, 112404
JP7 JP8 JP11 = HD1X2-079
JP9 = HD1X3: 1ST PART FIELD: SEL0; 2ND PART FIELD: 1; 3RD PART FIELD: 0
JP10 = HD1X3: 1ST PART FIELD: SEL1; 2ND PART FIELD: 1; 3RD PART FIELD: 0
RP1 RP2 = LT5400-4
U1 U2 = LTC2500IDKD-DFN24DKD-7X4
U11 U16 = LTC6655AHMSH-5
U12 U17 = NL17SZ74-US8
U13 U18 = LT1468CS8-SO8
U14 U19 = LT1468CS8-SO8: IC, OP AMP, 90 MHZ, SOIC (OPTION); OPT: OPT
U15 U20 = LT1637_SOIC
X1 = HI_FREQ_TESTPOINT-_70_30_PAD: PART FIELD 1: VCM1
C56 C133 C135 = CAP-NP: VOLTAGE: 16V
C69 = CAP-NP: VOLTAGE: 6.3V
E2 = E-064: PART FIELD 1: VREF2
J6 = BNC_1: CONNECTOR, BNC; PART FIELD 1: AIN+ 2; PART FIELD 2: +/- 10V; Part Number: CONNEX, 112404
J7 = BNC_1: CONNECTOR, BNC; OPT: OPT; PART FIELD 1: AIN- 2; PART FIELD 2: +/- 10V; Part Number: CONNEX, 112404
X2 = HI_FREQ_TESTPOINT-_70_30_PAD: PART FIELD 1: VCM2
E3 = E-064: PART FIELD 1: +3.3V
J9 = SMA-CON: 1ST PART FIELD: CLOCK IN; OPT: OPT
U21 = LTC6954EUFF-QFN36UFF-4X7_0: 1st Part Field: *
Y1 = Y-ECS-LVDS33-2000-BN_0
C134 = CAP-NP: 10V: 25V; 1ST PART FIELD: X7R; VOLTAGE: 25V
C136 C138 = CAP-NP: 10V: 16V; 1ST PART FIELD: X7R
C137 = CAP-NP: 10V: 16V; 1ST PART FIELD: X7R; OPT: OPT
D1-D4 = BAT54S
D8 = DIODE-SCHOTTKY
E4 = E-064: PART FIELD 1: +2.5V
E5 = E-064: PART FIELD 1: +5V
E7 = E-064: PART FIELD 1: -5V
JP6 = HD1X2-079: 1ST PART FIELD: VIN; 2ND PART FIELD: OUT
L4 = IND-CLS62
U22 = LT3032EDE-DFN14DEMA
U23 = LT1761ES5-SOT23-2.5
U24 = LTC4217IDHC-12-DFN16DHC-5X3
U29 = LT1931ES5-SOT23-5_0
U30 = LT3042EDD-DFN10DD-3X3
C115 = TMK212BJ475MG: 1ST PART FIELD: <1st Part Field>; VOLTAGE: 16V
C118 C121 = CAP-NP: 1st Part Field: 16V
C122 = CAP-NP: 1st Part Field: 25V; 3rd Part Field: X5R
D5 D7 = DIODE-DFLS1200-POWERDI123: 5th Part Field: DFLS120-7
D6 = DIODE-DFLS1200-POWERDI123: 6th Part Field: OPT; OPT: OPT
E11 = E-064: 10th Part Field: 12V; 9th Part Field: VIN
E12 E14 = E-064: 10th Part Field: 12V / 300mA; 9th Part Field: GND
E13 = E-064: 10th Part Field: 15V / 300mA; 9th Part Field: V+
E15 = E-064: 10th Part Field: -15V / 200mA; 9th Part Field: V-
J8 = JACK-CUI-PJ-002AH: OPT: OPT; PART FIELD 1: VIN
JP5 = HD1X3: PART FIELD 1: OUTPUT; PART FIELD 2: ON; PART FIELD 3: OFF
L1 = NR4018T100M
L2 L3 = NR4012T150M
R139 R141 R143 = R: 2nd Part Field: 1%
U27 = LT3471EDD-DFN10DD-3X3

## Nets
12VHSMC: P1.46(12V) P1.52(12V) P1.58(12V) P1.64(12V) P1.70(12V) P1.76(12V) P1.82(12V) P1.88(12V) P1.94(12V) P1.100(12V) P1.106(12V) P1.112(12V) P1.118(12V) P1.124(12V) P1.130(12V) P1.136(12V) P1.142(12V) P1.148(12V) P1.154(12V) U24.1(VDD) U24.16(VDD)
+2.5V: C36.1 C37.2 C60.1 C61.2 C106.1 C108.1 E4.1(A) R134.1 U1.3(VDD) U2.3(VDD) U23.5(OUT)
+3.3V: C27.2 C28.2 C29.1 C38.2 C39.1 C54.1 C62.2 C63.1 C79.2 C80.2 C81.2 C82.2 C83.2 C84.2 C85.2 C86.2 C87.2 C88.2 C89.2 C90.2 C91.2 C92.2 C93.2 C94.2 C95.2 C96.2 C97.2 C100.1 C103.1 C153.2 E3.1(A) FB1.2 J1.2(5V) JP9.3 JP10.3 R70.2 R71.2 R72.2 R73.2 R112.1 R118.2 R121.2 R124.1 R125.1 U1.22(OVDD) U2.22(OVDD) U9.8(VCC) U10.1(A0) U10.8(VCC) U12.6(~{CLR}) U12.8(VCC) U17.6(~{CLR}) U17.8(VCC) U21.1(V+OUT2) U21.4(V+OUT2) U21.5(V+OUT1) U21.8(V+OUT1) U21.9(V+OUT0) U21.12(V+OUT0) U21.15(V+A) U21.18(V+D) U21.21(V+D) U21.23(V+A) U21.24(V+A) U21.25(V+IN) U21.30(V+IN) U21.34(V+A) Y1.6(VDD)
+3.3VHSMC: F1.1 P1.45(3V3) P1.51(3V3) P1.57(3V3) P1.63(3V3) P1.69(3V3) P1.75(3V3) P1.81(3V3) P1.87(3V3) P1.93(3V3) P1.99(3V3) P1.105(3V3) P1.111(3V3) P1.117(3V3) P1.123(3V3) P1.129(3V3) P1.135(3V3) P1.141(3V3) P1.147(3V3) P1.153(3V3) P1.159(3V3)
+5V: C15.2 C16.2 C129.1 C130.1 D3.2 D4.2 E5.1(A) R1.2 U3.25(+VCC) U6.25(+VCC) U22.1(OUTP)
-5V: C1.1 C2.1 C8.1 C9.1 C21.1 C22.1 C127.1 C128.2 D3.1 D4.1 E7.1(A) U3.23(VEE) U6.23(VEE) U22.7(OUTN)
-6V: -6V.1 C133.1 C137.1 C138.1 FB2.1 L4.4(3) R154.1
GND: C3.1 C6.2 C7.1 C10.1 C13.2 C14.1 C15.1 C16.1 C17.1 C18.1 C19.1 C20.1 C21.2 C22.2 C23.2 C24.2 C25.2 C26.2 C27.1 C28.1 C29.2 C30.2 C31.2 C32.1 C33.2 C34.2 C35.2 C36.2 C37.1 C38.1 C39.2 C41.1 C42.2 C44.2 C45.1 C47.2 C48.2 C50.1 C51.2 C53.1 C54.2 C55.2 C56.2 C57.1 C58.2 C59.2 C60.2 C61.1 C62.1 C63.2 C64.2 C66.1 C67.2 C69.2 C70.1 C72.2 C73.2 C75.1 C76.2 C78.1 C79.1 C80.1 C81.1 C82.1 C83.1 C84.1 C85.1 C86.1 C87.1 C88.1 C89.1 C90.1 C91.1 C92.1 C93.1 C94.1 C95.1 C96.1 C97.1 C100.2 C103.2 C107.2 C108.2 C115.2 C117.2 C118.2 C120.2 C121.2 C124.2 C125.2 C128.1 C130.2 C131.2 C132.1 C133.2 C135.2 C136.2 C138.2 C139.2 C140.1 C141.2 C142.1 C144.2 C145.1 C146.1 C147.2 C148.2 C149.1 C150.2 C151.1 C152.2 C153.1 C154.1 C155.1 C156.1 C157.2 C158.2 CSS1.2 D1.3 D2.3 D3.3 D4.3 D7.1 D8.1 E8.1(A) E9.1(A) E10.1(A) E12.1(A) E14.1(A) J1.3(GND) J1.8(GND) J1.12(EEGND) J2.2 J2.3 J2.4 J2.5 J3.2 J3.3 J3.4 J3.5 J4.2 J4.3 J4.4 J4.5 J5.2 J5.3 J5.4 J5.5 J6.2 J6.3 J6.4 J6.5 J7.2 J7.3 J7.4 J7.5 J8.2 J8.3 J9.2 J9.3 J9.4 J9.5 JP2.1 JP5.3 JP9.1 JP10.1 P1.161(GND) P1.162(GND) P1.163(GND) P1.164(GND) P1.165(GND) P1.166(GND) P1.167(GND) P1.168(GND) P1.169(GND) P1.170(GND) P1.171(GND) P1.172(GND) R6.1 R81.2 R82.2 R91.2 R92.2 R100.2 R101.2 R110.2 R111.2 R113.2 R116.1 R126.2 R127.2 R134.2 R141.1 R142.2 R151.1 R152.1 R155.2 R159.1 R163.1 R164.2 R167.2 R168.2 RP1.9 RP2.9 U1.4(GND) U1.7(GND) U1.23(GND) U1.24(GND) U1.25(EP) U2.4(GND) U2.7(GND) U2.23(GND) U2.24(GND) U2.25(EP) U3.17(AGND) U3.18(LADCOM) U3.24(DGND) U4.3(+IN_A) U4.5(+IN_B) U6.17(AGND) U6.18(LADCOM) U6.24(DGND) U7.3(+IN_A) U7.5(+IN_B) U9.1(A0) U9.2(A1) U9.3(A2) U9.4(GND) U10.2(A1) U10.3(A2) U10.4(GND) U11.3(GND) U11.4(GND) U11.5(GND) U11.8(GND) U12.2(D) U12.4(GND) U16.3(GND) U16.4(GND) U16.5(GND) U16.8(GND) U17.2(D) U17.4(GND) U21.14(GND) U21.26(GND) U21.29(GND) U21.32(GND) U21.35(GND) U21.37(GND) U22.4(GND) U22.5(GND) U22.15(EP1) U23.2(GND) U24.6(GND) U27.11(EP) U29.2(GND) U30.8(GND) U30.11(EP) Y1.3(GND)
VIN: C115.1 C135.1 C136.1 C157.1 E11.1(A) FB3.1 J8.1 JP6.2 L1.1 L2.1 L4.3 U27.8(VIN) U29.5(VIN)
ADC_CLK1: R117.1 U12.1(CP)
ADC_CLK2: R119.1 U17.1(CP)
AMPV+: C32.2 C50.2 C57.2 C75.2 C149.2 E18.1(A) JP7.1 U13.7(V+) U14.7(V+) U18.7(V+) U19.7(V+)
AMPV-: C41.2 C53.2 C66.2 C78.2 C150.1 E19.1(A) JP8.1 U13.4(V-) U14.4(V-) U18.4(V-) U19.4(V-)
BUSY1: R19.1 U1.21(BUSY)
BUSY2: R41.1 U2.21(BUSY)
CLK_SYNC: R9.1 R116.2 U21.22(SYNC) X3.1
CONV1: R31.1 R76.1 U12.7(~{PR})
CONV2: R52.1 R95.1 U17.7(~{PR})
DAC_CLK1: R114.1 U3.26(CLK)
DAC_CLK2: R115.1 U6.26(CLK)
DRDY1#: R29.1 U1.15(~{DRDY})
DRDY2#: R50.1 U2.15(~{DRDY})
FLT: U24.2(UV) U24.12(~{FLT})
FPGA_CLK1: P1.98(CLKIN1N) R122.1
FPGA_CLK2: P1.96(CLKIN1P) R123.1
LIN_SENSE: J1.13(GND) R8.1 R73.1
LTC6954_CS#: R60.1 U21.16(~{CS})
LTC6954_MISO: R57.1 U21.17(SDO)
LTC6954_MOSI: R56.1 U21.20(SDI)
LTC6954_SCK: R61.1 U21.19(SCLK)
MCLK1: R75.1 R76.2 U1.13(MCLK)
MCLK2: R94.1 R95.2 U2.13(MCLK)
OUT1: J2.1 R2.2 R170.2
OUT2: J3.1 R5.2 R171.2
PG: JP5.1 R150.2 U24.11(PG) U29.4(~{SHDN})
RDLA1: R18.1 U1.1(RDLA)
RDLA2: R40.1 U2.1(RDLA)
RDLB1: R17.1 U1.2(RDLB)
RDLB2: R36.1 U2.2(RDLB)
SCKA1: R22.1 U1.18(SCKA)
SCKA2: R46.1 U2.18(SCKA)
SCKB1: R21.1 U1.19(SCKB)
SCKB2: R45.1 U2.19(SCKB)
SCL: P1.34(SCL) R70.1 U9.6(SCL) U10.6(SCL)
SDA: P1.33(SDA) R71.1 U9.5(SDA) U10.5(SDA)
SDI1: R25.1 U1.16(SDI)
SDI2: R49.1 U2.16(SDI)
SDOA1: R28.1 U1.17(SDOA)
SDOA2: R48.1 U2.17(SDOA)
SDOB1: R20.1 U1.20(SDOB)
SDOB2: R42.1 U2.20(SDOB)
SEL0: JP9.2 U1.11(GND) U2.11(GND)
SEL1: JP10.2 U1.12(GND) U2.12(GND)
SENSE_5V: R1.1 R6.2 R7.1
SYNC1: R30.1 U1.14(SYNC)
SYNC2: R51.1 U2.14(SYNC)
TEMP: U21.31(TEMP) X4.1
V+: C17.2 C18.2 C19.2 C20.2 C42.1 C67.1 C118.1 C145.2 C146.2 C151.2 D1.2 D2.2 E13.1(A) FB4.2 JP7.2 R4.1 R39.1 U4.8(V+) U5.1 U7.8(V+) U8.1 U15.7(V+) U20.7(V+)
V-: C23.1 C24.1 C25.1 C26.1 C48.1 C73.1 C121.1 C147.1 C148.1 C152.1 D1.1 D2.1 E15.1(A) FB5.2 JP8.2 U4.4(V-) U5.6 U5.9 U7.4(V-) U8.6 U8.9 U15.4(V-) U20.4(V-)
VCM1: C44.1 R80.2 R82.1 U15.3(+IN) X1.1
VCM2: C69.1 R99.2 R101.1 U20.3(+IN) X2.1
VPREREG: C107.1 C131.1 C155.2 C158.1 R68.2 R128.1 R149.2 R165.2 U22.10(\~{SHDNN}) U22.14(INP) U23.1(VIN) U30.9(OUTS) U30.10(OUT)
VREF1: C33.1 C34.1 E1.1(A) R3.2 R10.2 R33.1 R74.2 R80.1 R158.1 U1.8(REF) U1.9(REF)
VREF2: C58.1 C59.1 E2.1(A) R37.2 R38.2 R62.1 R93.2 R99.1 R162.1 U2.8(REF) U2.9(REF)
WP: JP2.2 U9.7(WP) U10.7(WP)
N2695982: C52.2 R90.2 R92.1 U14.2(-IN)
N2695986: C52.1 R89.1 R90.1 R91.1 R146.2 U14.6(OUT)
N2695990: C47.1 R86.2 R89.2 R157.2 RP1.4
N2696068: C46.1 C140.2 R156.1 RP1.7 RP1.8 U1.5(IN+)
N2696096: C45.2 R78.2 R83.1 R156.2 RP1.1
N2696108: C49.2 R84.1 R85.1 R87.2 U15.6(OUT)
N2696124: C51.1 R88.2 R146.1 U14.3(+IN)
N2696244: C46.2 C139.1 R157.1 RP1.5 RP1.6 U1.6(IN-)
N2696248: C30.1 R74.1 U11.6(VOUT_S) U11.7(VOUT_F)
N2696362: C40.1 R78.1 R79.1 R145.2 U13.6(OUT)
N2696418: C35.1 R77.2 R145.1 U13.3(+IN)
N2696434: C40.2 R79.2 R81.1 U13.2(-IN)
N2696470: R84.2 RP1.2
N2696570: R85.2 RP1.3
N2696590: C49.1 R83.2 R86.1 R87.1 U15.2(-IN)
N2697380: C31.1 R68.1 U11.1(~{SHDN}) U11.2(VIN)
N2698312: J5.1 R88.1
N2698360: J4.1 R77.1
N18064202: P1.151(LVDS_TXN16) U3.14(DB0(LSB))
N18064223: P1.86(LVDS_RXN6) R41.2
N18064225: C5.2 R10.1 R14.2 R24.1 R27.2 U4.6(-IN_B)
N18064248: P1.149(LVDS_TXP16) U3.13(DB1)
N18064356: P1.145(LVDS_TXN15) U3.12(DB2)
N18064358: P1.84(LVDS_RXP6) R42.2
N18064403: P1.80(LVDS_RXN5) R45.2
N18064418: P1.78(LVDS_RXP5) R46.2
N18064437: P1.143(LVDS_TXP15) U3.11(DB3)
N18064455: P1.74(LVDS_RXN4) R48.2
N18064464: P1.139(LVDS_TXN14) U3.10(DB4)
N18064488: P1.91(LVDS_TXN7) U6.14(DB0(LSB))
N18064502: P1.137(LVDS_TXP14) U3.9(DB5)
N18064511: P1.72(LVDS_RXP4) R49.2
N18064513: P1.156(CLKIN2P) R8.2
N18064519: P1.41(D0) R66.2
N18064562: P1.68(LVDS_RXN3) R50.2
N18064564: P1.152(LVDS_RXN16) X6.1
N18064570: J1.4(SCK/SCL) R66.1
N18064597: R2.1 R24.2 R170.1 U5.3
N18064601: P1.150(LVDS_RXP16) X5.1
N18064639: P1.85(LVDS_TXN6) U6.12(DB2)
N18064641: P1.83(LVDS_TXP6) U6.11(DB3)
N18064656: P1.79(LVDS_TXN5) U6.10(DB4)
N18064658: P1.77(LVDS_TXP5) U6.9(DB5)
N18064682: P1.73(LVDS_TXN4) U6.8(DB6)
N18064706: P1.71(LVDS_TXP4) U6.7(DB7)
N18064741: P1.67(LVDS_TXN3) U6.6(DB8)
N18064743: P1.66(LVDS_RXP3) R51.2
N18064805: P1.65(LVDS_TXP3) U6.5(DB9)
N18064807: P1.61(LVDS_TXN2) U6.4(DB10)
N18064812: P1.59(LVDS_TXP2) U6.3(DB11)
N18064822: P1.55(LVDS_TXN1) U6.2(DB12)
N18064826: P1.53(LVDS_TXP1) U6.1(DB13)
N18064845: P1.49(LVDS_TXN0) U6.28(DB14)
N18064861: P1.47(LVDS_TXP0) U6.27(DB15(MSB))
N18064938: P1.146(LVDS_RXN15) R9.2
N18064950: P1.62(LVDS_RXN2) R52.2
N18064982: P1.144(LVDS_RXP15) X7.1
N18064990: R33.2 R34.1 U3.16(IREFIN)
N18064996: P1.60(LVDS_RXP2) R53.2
N18064998: J1.5(MISO) R64.1
N18065000: P1.140(LVDS_RXN14) X8.1
N18065041: P1.133(LVDS_TXN13) U3.8(DB6)
N18065056: P1.56(LVDS_RXN1) R56.2
N18065066: P1.138(LVDS_RXP14) X9.1
N18065084: J1.7(MOSI/SDA) R65.1
N18065088: P1.131(LVDS_TXP13) U3.7(DB7)
N18065111: P1.134(LVDS_RXN13) R17.2
N18065117: C2.2 U3.22(COMP2)
N18065127: P1.54(LVDS_RXP1) R57.2
N18065169: P1.132(LVDS_RXP13) R18.2
N18065182: C1.2 U3.21(COMP1)
N18065186: P1.127(LVDS_TXN12) U3.6(DB8)
N18065225: P1.50(LVDS_RXN0) R60.2
N18065235: P1.158(CLKIN2N) R7.2
N18065245: P1.43(D2) R67.2
N18065283: P1.128(LVDS_RXN12) R19.2
N18065285: P1.125(LVDS_TXP12) U3.5(DB9)
N18065312: C6.1 R34.2 U3.15(REFOUT)
N18065322: P1.48(LVDS_RXP0) R61.2
N18065343: J1.6(~{CS}) R67.1
N18065345: P1.126(LVDS_RXP12) R20.2
N18065349: P1.121(LVDS_TXN11) U3.4(DB10)
N18065395: P1.122(LVDS_RXN11) R21.2
N18065400: P1.119(LVDS_TXP11) U3.3(DB11)
N18065437: P1.120(LVDS_RXP11) R22.2
N18065461: P1.115(LVDS_TXN10) U3.2(DB12)
N18065486: P1.116(LVDS_RXN10) R28.2
N18065508: P1.113(LVDS_TXP10) U3.1(DB13)
N18065518: P1.114(LVDS_RXP10) R25.2
N18065552: P1.110(LVDS_RXN9) R29.2
N18065554: P1.109(LVDS_TXN9) U3.28(DB14)
N18065589: P1.108(LVDS_RXP9) R30.2
N18065607: P1.107(LVDS_TXP9) U3.27(DB15(MSB))
N18065609: C4.2 JP1.3 R3.1 R16.2 R23.1 U4.2(-IN_A)
N18065623: P1.89(LVDS_TXP7) U6.13(DB1)
N18065645: C4.1 R14.1 R23.2 U4.1(OUT_A)
N18065649: C5.1 U4.7(OUT_B) U5.8
N18065663: P1.104(LVDS_RXN8) R31.2
N18065721: P1.102(LVDS_RXP8) R32.2
N18065901: P1.92(LVDS_RXN7) R36.2
N18065950: P1.90(LVDS_RXP7) R40.2
N18697302: R124.2 R126.1 U21.33(OUT1SEL)
N18697346: R125.2 R127.1 U21.36(OUT2SEL)
N18697467: R117.2 U21.7(OUT1+)
N18697489: R123.2 U21.2(OUT2-)
N18697502: R112.2 R113.1 U21.13(OUT0SEL)
N18697515: R114.2 U21.11(OUT0+)
N18697549: R115.2 U21.10(OUT0-)
N18698005: R122.2 U21.3(OUT2+)
N18698013: C99.1 R120.1 Y1.5(C-OUT)
N18698493: C98.2 C143.2 U21.27(IN+)
N18698495: C99.2 C144.1 U21.28(IN-)
N18700476: CSS1.1 RSS1.2 U27.7(\\~{SHD}N/SS2) U27.9(\\~{SHD}N/SS1)
N18700541: C124.1 R144.2 U27.2(FBIP) U27.3(VREF)
N18700567: C123.1 R143.1 R144.1 U27.4(FB2P)
N18700589: C116.1 C117.1 D5.1 JP11.1 R139.1
N18700595: C116.2 R139.2 R141.2 U27.1(FBIN)
N18700609: C119.1 C120.1 C123.2 D6.1 FB5.1 L3.1 R140.1 R143.2
N18700626: C122.2 D7.2 L3.2
N18700652: C119.2 R140.2 R142.1 U27.5(FB2N)
N18700793: JP5.2 RSS1.1
N18700860: C122.1 D6.2 L2.2 U27.6(SW2)
N19263844: R12.1 U3.19(IOUTB)
N19265101: R26.1 U3.20(IOUTA)
N19267636: C3.2 R12.2 R16.1
N19268271: C7.2 R26.2 R27.1
N19437822: R62.2 R63.1 U6.16(IREFIN)
N19437840: C12.2 R37.1 R43.2 R54.1 U7.2(-IN_A)
N19437876: R5.1 R35.2 R55.2 R171.1 U8.3
N19437880: C13.1 R63.2 U6.15(REFOUT)
N19437884: C11.1 U7.7(OUT_B) U8.8
N19437912: C11.2 R38.1 R44.2 R55.1 R59.2 U7.6(-IN_B)
N19437916: C12.1 R44.1 R54.2 U7.1(OUT_A)
N19437918: R47.1 U6.19(IOUTB)
N19437940: R58.1 U6.20(IOUTA)
N19437962: C10.2 R43.1 R47.2
N19437996: C14.2 R58.2 R59.1
N19438026: C9.2 U6.22(COMP2)
N19438032: C8.2 U6.21(COMP1)
N19526979: F1.2 FB1.1
N19826447: C98.1 R120.2 Y1.4(OUT)
N19844952: R121.1 Y1.2(NC)
N19848175: R118.1 Y1.1(TRI-STATE)
N19881075: R119.2 U21.6(OUT1-)
N19977188: D5.2 L1.2 U27.10(SW1)
N20575683: C55.1 R93.1 U16.6(VOUT_S) U16.7(VOUT_F)
N20575689: C74.1 R103.2 R105.1 R106.1 U20.2(-IN)
N20575711: C76.1 R108.2 R148.1 U19.3(+IN)
N20575747: C74.2 R102.1 R104.1 R106.2 U20.6(OUT)
N20575774: C77.2 R109.2 R111.1 U19.2(-IN)
N20575776: C77.1 R107.1 R109.1 R110.1 R148.2 U19.6(OUT)
N20575778: C72.1 R105.2 R107.2 R161.2 RP2.4
N20575817: C71.1 C142.2 R160.1 RP2.7 RP2.8 U2.5(IN+)
N20575819: C70.2 R97.2 R103.1 R160.2 RP2.1
N20575863: C71.2 C141.1 R161.1 RP2.5 RP2.6 U2.6(IN-)
N20575902: C65.1 R97.1 R98.1 R147.2 U18.6(OUT)
N20575928: C64.1 R96.2 R147.1 U18.3(+IN)
N20575932: C65.2 R98.2 R100.1 U18.2(-IN)
N20575950: R102.2 RP2.2
N20575992: R104.2 RP2.3
N20576140: C56.1 R149.1 U16.1(~{SHDN}) U16.2(VIN)
N20576358: J7.1 R108.1
N20576372: J6.1 R96.1
N20667454: C106.2 U23.4(BYP)
N20929289: R32.1 X10.1
N20954558: R158.2 R159.2 U1.10(PRE)
N20956477: R162.2 R163.2 U2.10(PRE)
N21019287: P1.38(JTAG_TDI) R69.1
N21020818: P1.37(JTAG_TDO) R69.2
N21248036: JP2.3 R72.1
N21334947: JP1.2 R35.1
N21696941: P1.42(D1) R65.2
N21696944: P1.44(D3) R64.2
N21701920: R128.2 U23.3(~{SHDN})
N21705400: C125.1 FB2.2 U22.6(INN) U22.9(INN) U22.16(EP2)
N21705450: C127.2 U22.11(BYPN)
N21705579: C129.2 U22.3(BYPP)
N21780800: C134.2 L4.2 U29.1(SW)
N21780841: C137.2 R154.2 R155.1 U29.3(NFB)
N21780937: C134.1 D8.2 L4.1(2)
N21793941: JP6.1 R150.1 U24.7(OUT) U24.8(OUT) U24.9(OUT)
N21793971: R151.2 U24.15(ISET)
N21793981: IMON.1 R152.2 U24.14(IMON)
N21794013: R153.1 U24.4(TIMER)
N21794015: C132.2 R153.2 U24.5(INTVCC)
N21795874: J1.14(AUX) R53.1
N21813066: C143.1 J9.1 R164.1
N21815062: R165.1 U22.12(\~{SHDNP})
N21817750: P1.160(12V) X11.1
N21842260: TP1.1 U24.17(SENSE)
N21851257: FB4.1 JP11.2
N21863742: C154.2 FB3.2 R166.1 R169.2 U30.1(IN) U30.2(IN) U30.3(EN/UV)
N21864452: R166.2 U30.4(PG)
N21864650: R167.1 U30.5(ILIM)
N21866466: C156.2 R168.1 U30.7(SET)
N21866568: R169.1 U30.6(PGFB)
N21882185: R75.2 U12.3(~{Q})
N21882637: R94.2 U17.3(~{Q})
N21883789: R4.2 U5.2
N21883792: R39.2 U8.2

Not connected (* = marked no-connect by the designer): J1 1(V+)* 9(EESDA)* 10(EEVCC)* 11(EESCL)*; JP1 1*; P1 1(XCVR_TXP7)* 2(XCVR_RXP7)* 3(XCVR_TXN7)* 4(XCVR_RXN7)* 5(XCVR_TXP6)* 6(XCVR_RXP6)* 7(XCVR_TXN6)* 8(XCVR_RXN6)* 9(XCVR_TXP5)* 10(XCVR_RXP5)* 11(XCVR_TXN5)* 12(XCVR_RXN5)* 13(XCVR_TXP4)* 14(XCVR_RXP4)* 15(XCVR_TXN4)* 16(XCVR_RXN4)* 17(XCVR_TXP3)* 18(XCVR_RXP3)* 19(XCVR_TXN3)* 20(XCVR_RXN3)* 21(XCVR_TXP2)* 22(XCVR_RXP2)* 23(XCVR_TXN2)* 24(XCVR_RXN2)* 25(XCVR_TXP1)* 26(XCVR_RXP1)* 27(XCVR_TXN1)* 28(XCVR_RXN1)* 29(XCVR_TXP0)* 30(XCVR_RXPO)* 31(XCVR_TXN0)* 32(XCVR_RXN0)* 35(JTAG_TCK)* 36(JTAG_TMS)* 39(CLKOUT0)* 40(CLKIN0)* 95(CLKOUT1P)* 97(CLKOUT1N)* 101(LVDS_TXP8)* 103(LVDS_TXN8)* 155(CLKOUT2P)* 157(CLKOUT2N)*; U12 5(Q)*; U13 1(OFFSET1)* 5(OFFSET2)* 8(DNC)*; U14 1(OFFSET1)* 5(OFFSET2)* 8(DNC)*; U15 1(OFFSET1)* 5(OFFSET2)* 8(DNC)*; U17 5(Q)*; U18 1(OFFSET1)* 5(OFFSET2)* 8(DNC)*; U19 1(OFFSET1)* 5(OFFSET2)* 8(DNC)*; U20 1(OFFSET1)* 5(OFFSET2)* 8(DNC)*; U22 2(NC+/ADJP)* 8(ADJN/NC++)* 13(NC)*; U24 3(OV)* 10(GATE)* 13(FB)*

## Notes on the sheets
sheet 1
- (4)
- (4)
- (2)
- (4)
- (4)
- (3)
- (4)
- (4)
- BYPASS CAPACITORS
- ADDR : OX A0
- NOTES:  UNLESS OTHERWISE SPECIFIED
- 1.  ALL RESISTORS ARE IN OHMS, 0603.
- ALL CAPACITORS ARE IN MICROFARADS, 0603.
- 2.  INSTALL SHUNTS AS SHOWN.
- [3]. FOR U1 (PAGE 2) AND U2 (PAGE3):
- ASSY
- U1, U2
- SUFFIX
- -A
- LTC2500-32
- 00-32
- ADDR : OX A2
- -B
- TBD
- TBD
sheet 2
- (4)
- (1)
- (1)
- (1)
- (3)
- (3)
sheet 3
- (4)
- (1)
- (1)
- (1)
- (2)
sheet 4
- (1)
- (1)
- (1)
- (1)
- (1)
- (2)
- (3)
- (1)
- (1)
